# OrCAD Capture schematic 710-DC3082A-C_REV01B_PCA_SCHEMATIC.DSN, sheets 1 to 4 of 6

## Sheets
1 PAGE6: size A
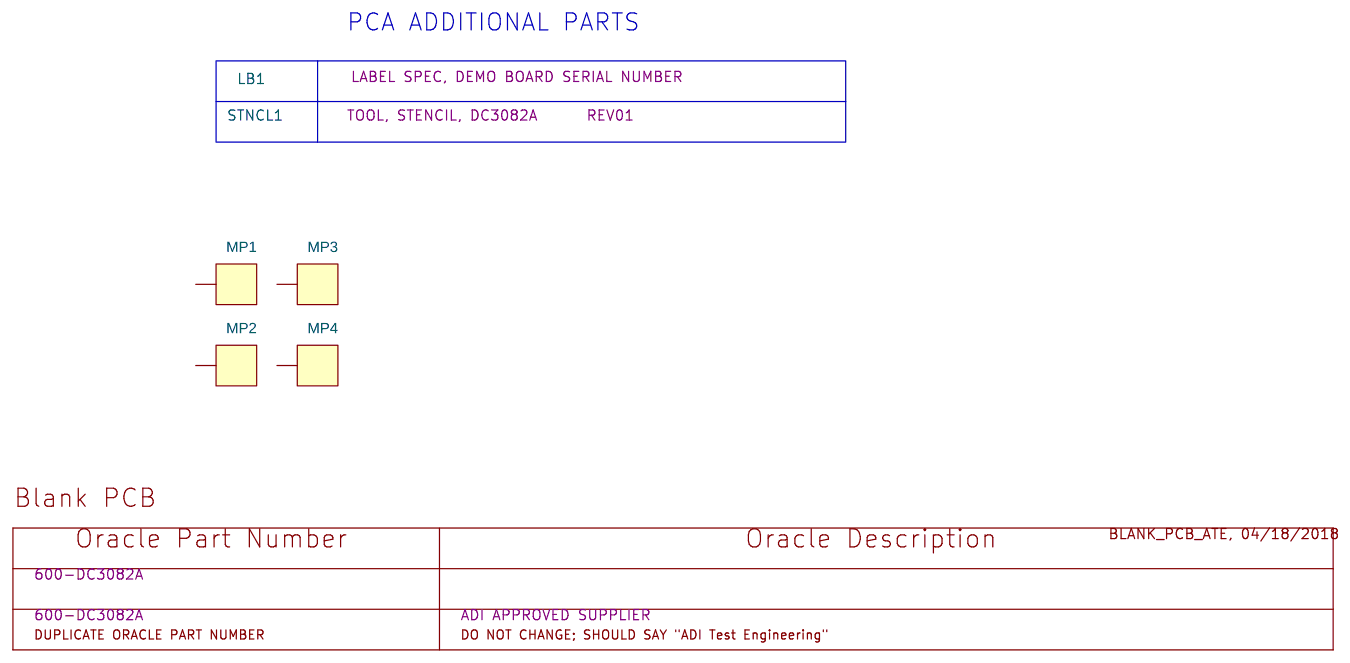
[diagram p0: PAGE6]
2 PAGE5: size Custom; rev: V1.0; company: WITH DIGITAL POWER MANAGEMENT; note: POLYPHASE SINGLE OUTPUT DC/DC PSM
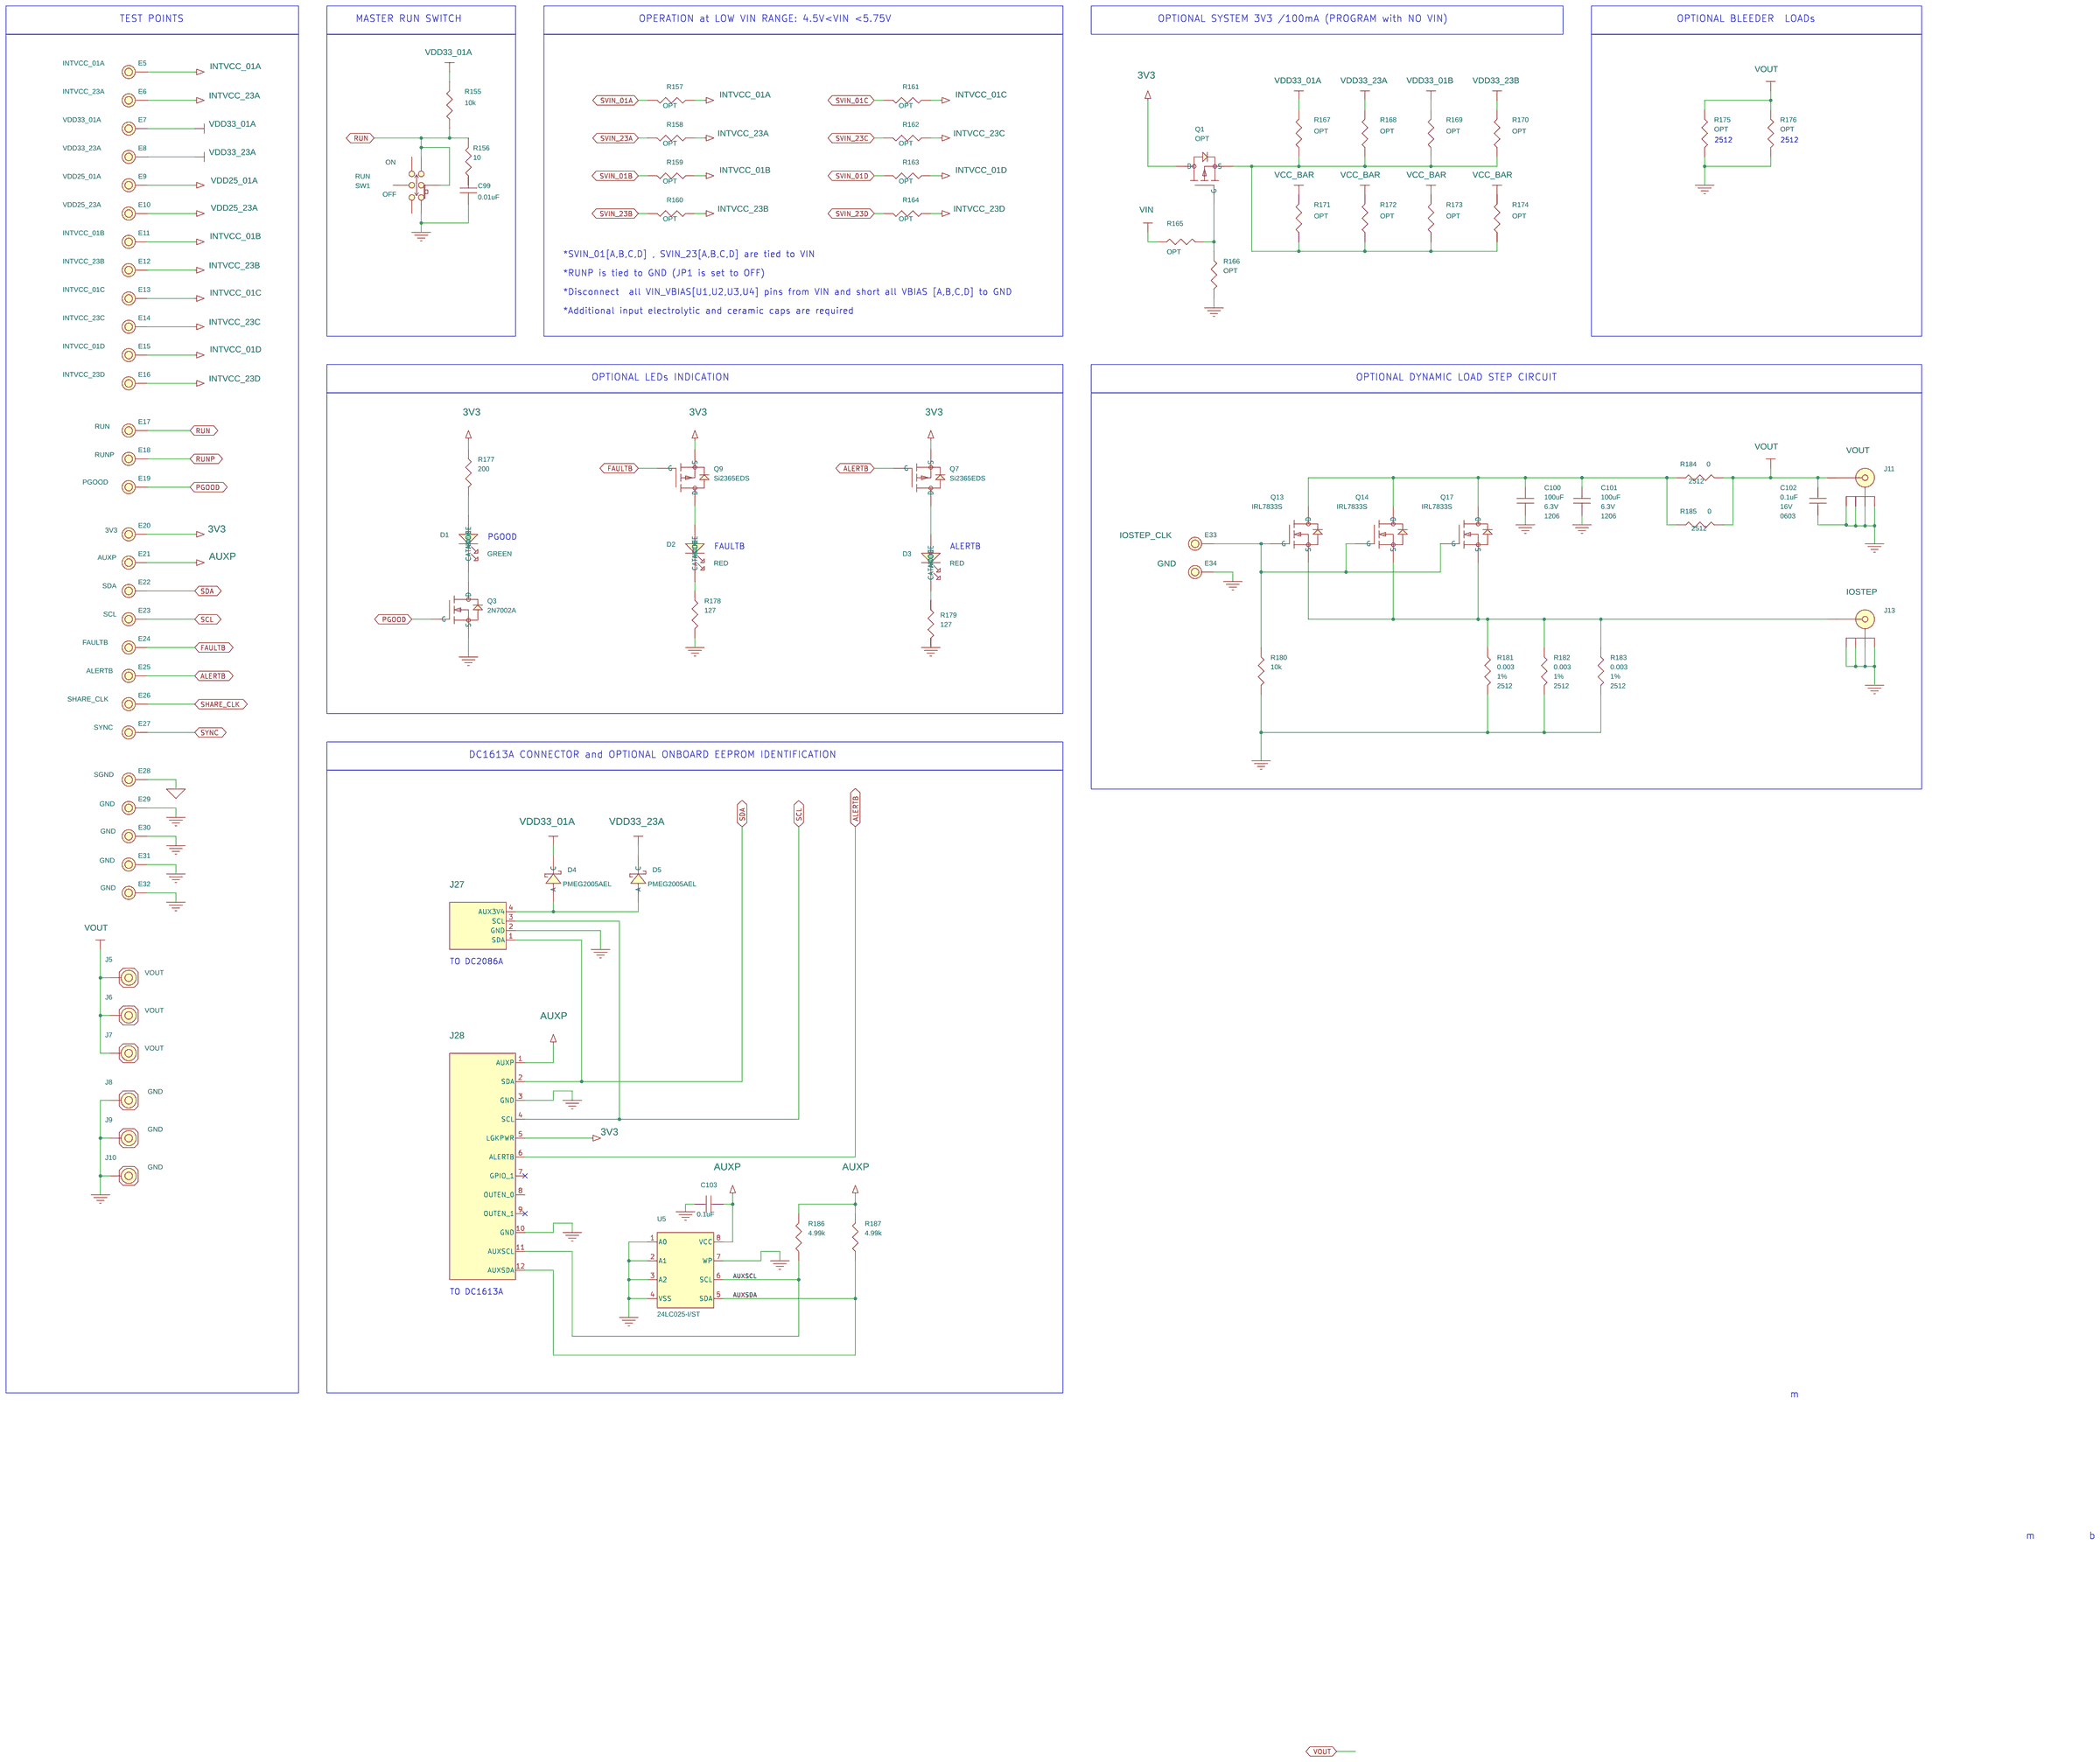
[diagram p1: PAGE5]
3 PAGE4: size Custom; rev: V1.0; company: WITH DIGITAL POWER MANAGEMENT; note: POLYPHASE SINGLE OUTPUT DC/DC PSM
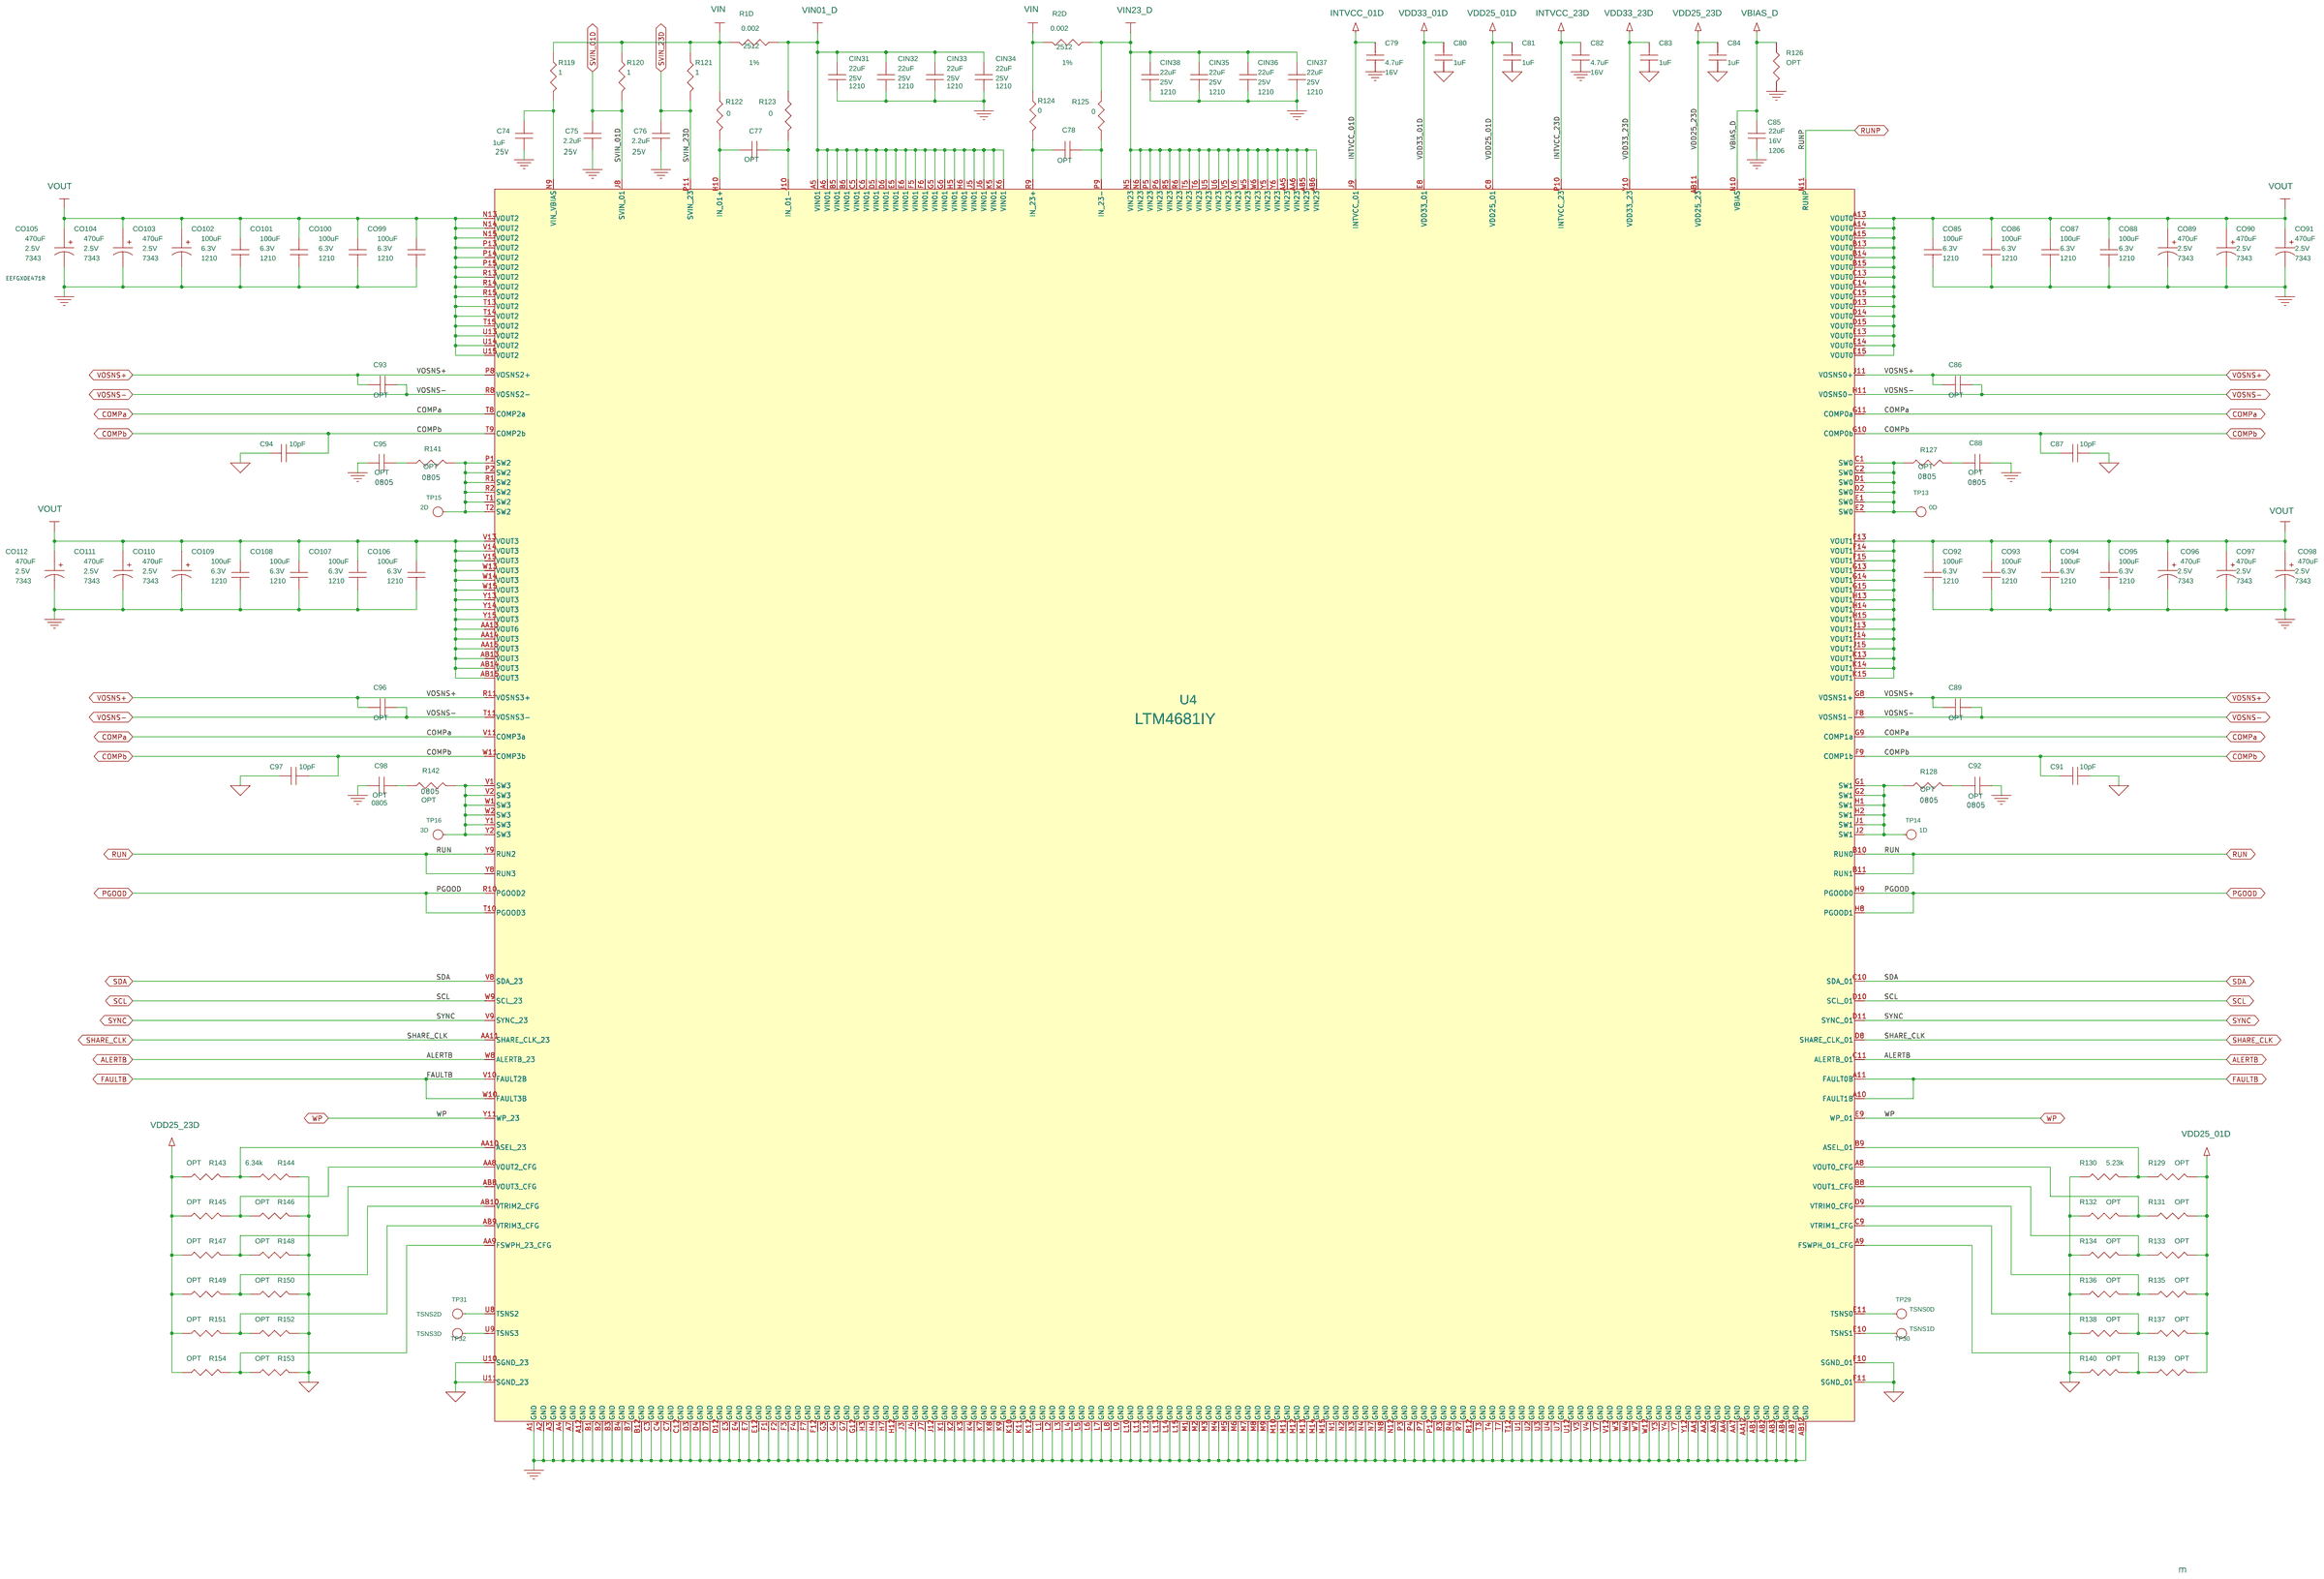
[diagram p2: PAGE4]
4 PAGE3: size Custom; rev: V1.0; company: WITH DIGITAL POWER MANAGEMENT; note: POLYPHASE SINGLE OUTPUT DC/DC PSM
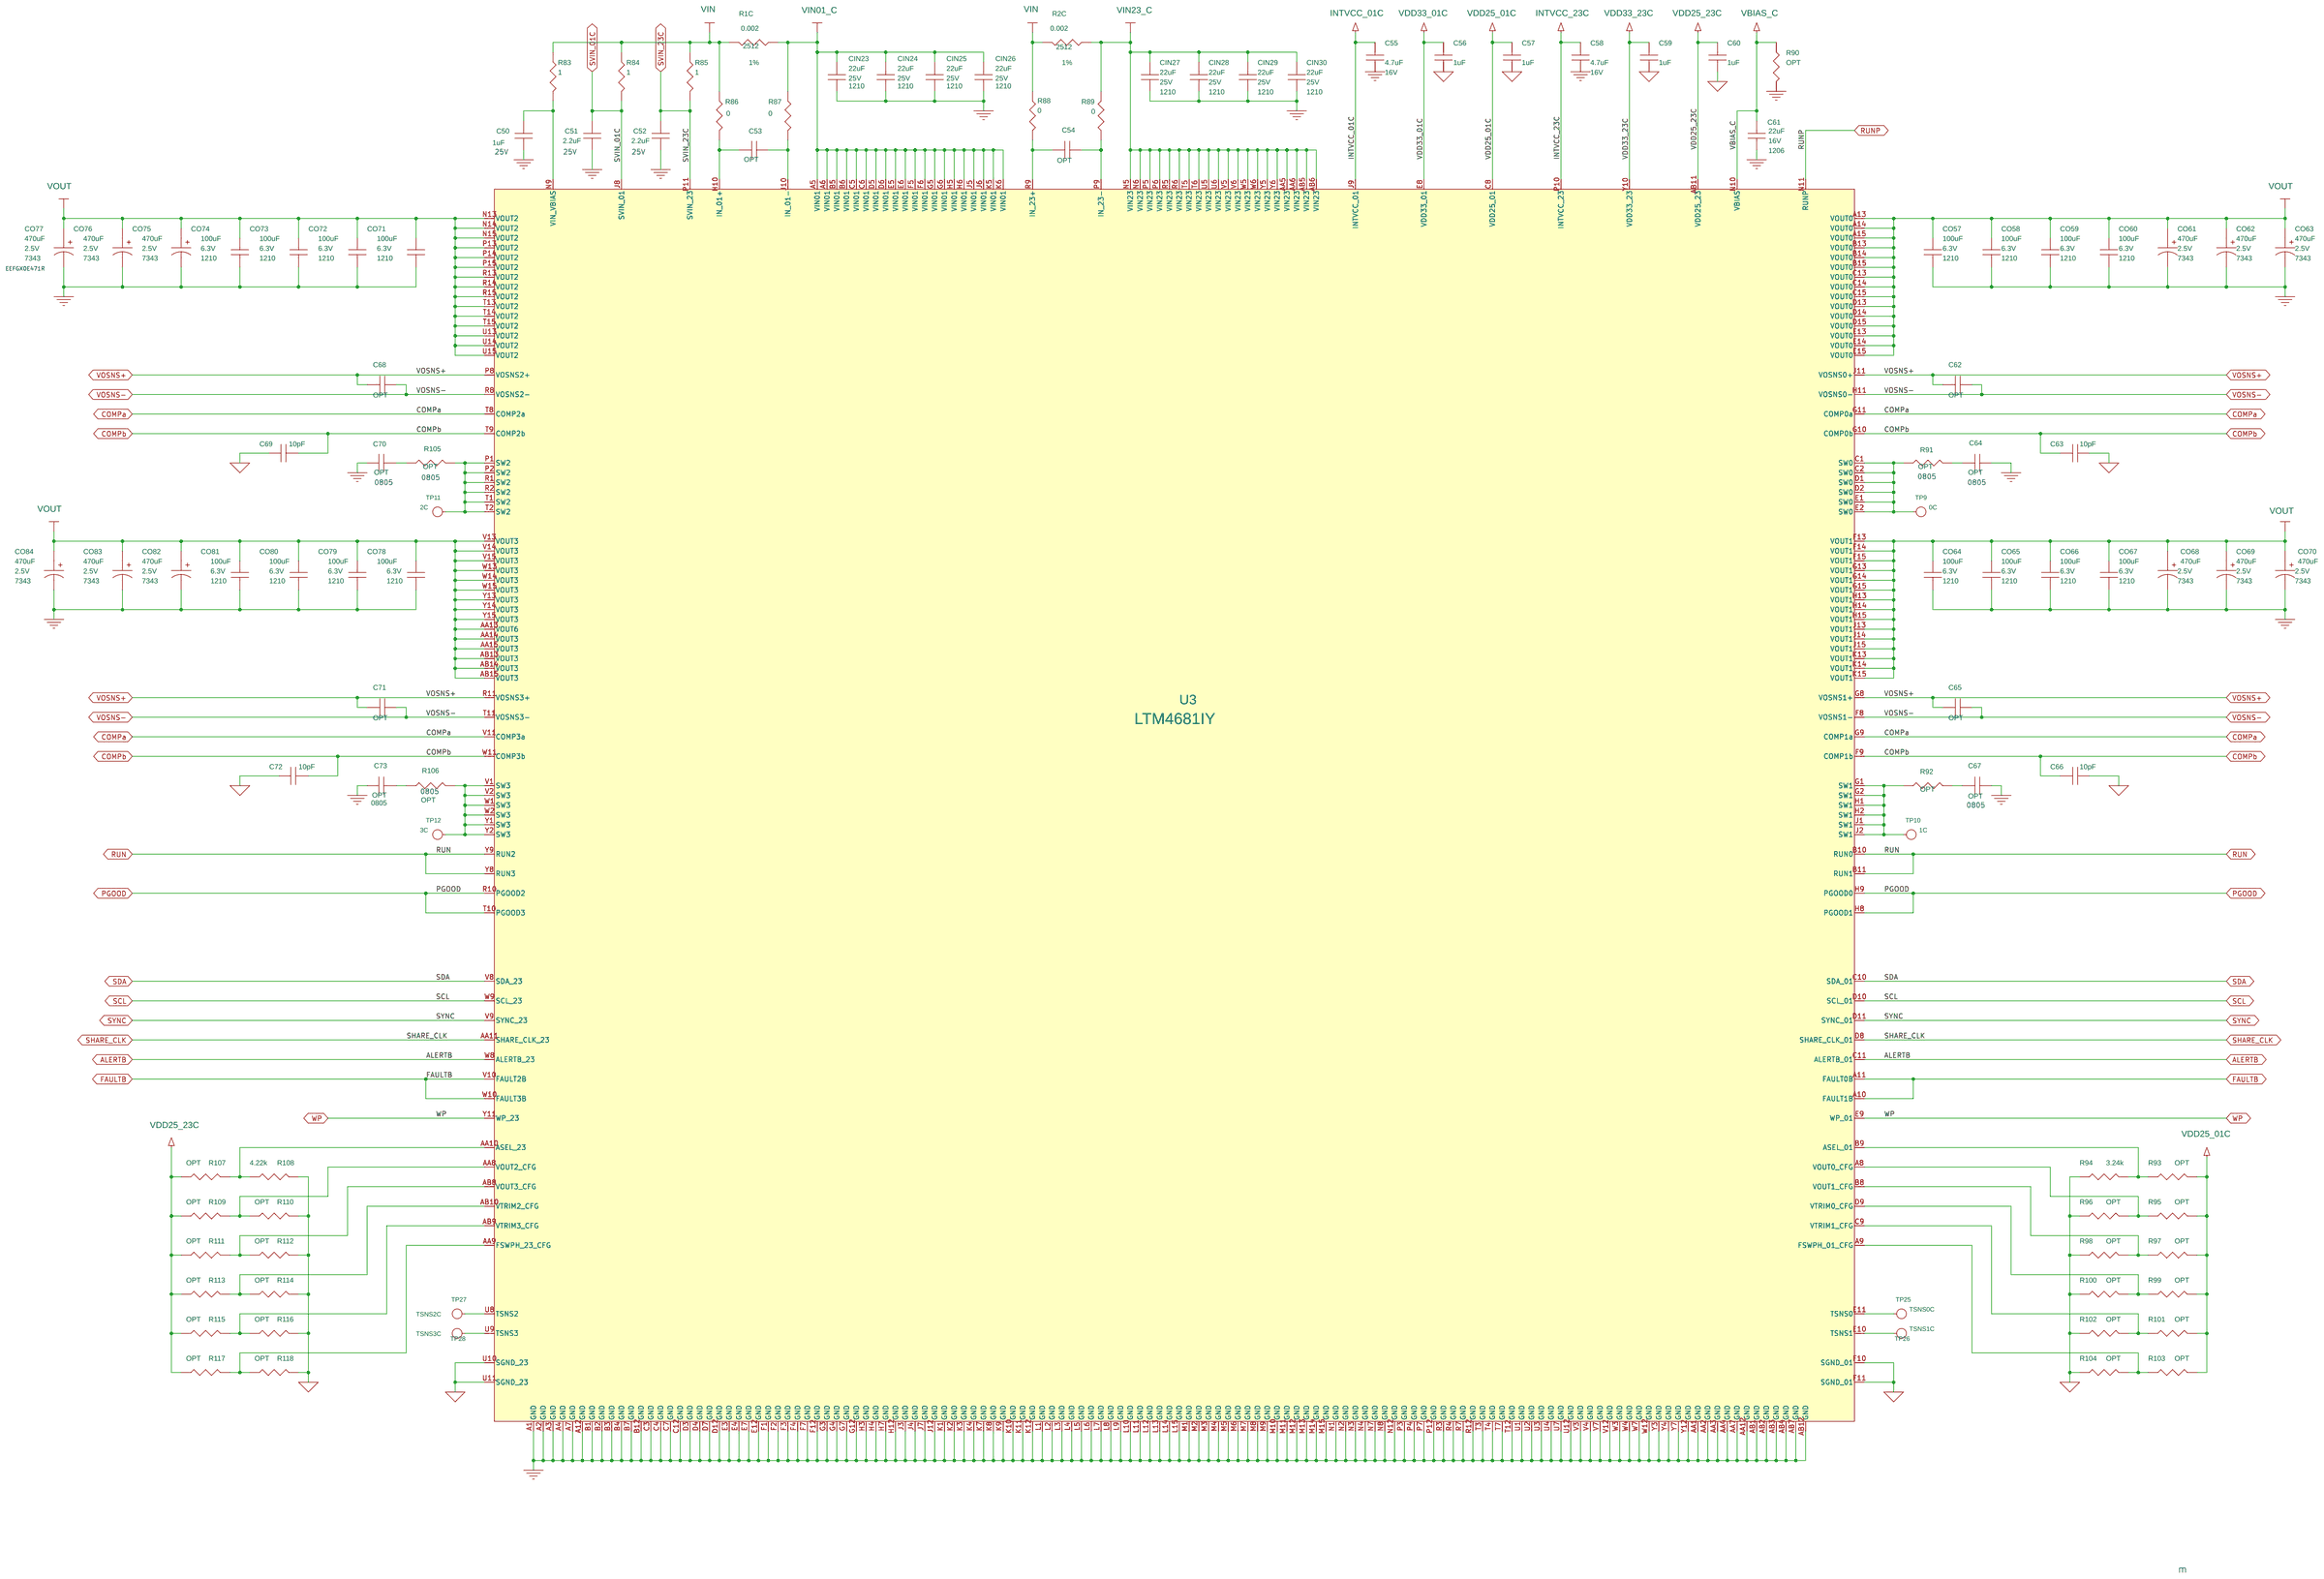
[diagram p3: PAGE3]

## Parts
sheet PAGE3
C50  1uF  [CC0603N]
C51  2.2uF  [CC0603N]
C52  2.2uF  [CC0603N]
C53  OPT  [CC0603N]
C54  OPT  [CC0603N]
C55  4.7uF  [CC0603N]
C56  1uF  [CC0603N]
C57  1uF  [CC0603N]
C58  4.7uF  [CC0603N]
C59  1uF  [CC0603N]
C60  1uF  [CC0603N]
C61  22uF  [CC1206N]
C62  OPT  [CC0603N]
C63  10pF  [CC0603N]
C64  OPT  [CC0805N]
C65  OPT  [CC0603N]
C66  10pF  [CC0603N]
C67  OPT  [CC0805N]
C68  OPT  [CC0603N]
C69  10pF  [CC0603N]
C70  OPT  [CC0805N]
C71  OPT  [CC0603N]
C72  10pF  [CC0603N]
C73  OPT  [CC0805N]
CIN23  22uF  [CC1210N]
CIN24  22uF  [CC1210N]
CIN25  22uF  [CC1210N]
CIN26  22uF  [CC1210N]
CIN27  22uF  [CC1210N]
CIN28  22uF  [CC1210N]
CIN29  22uF  [CC1210N]
CIN30  22uF  [CC1210N]
CO57  100uF  [CC1210N]
CO58  100uF  [CC1210N]
CO59  100uF  [CC1210N]
CO60  100uF  [CC1210N]
CO61  470uF  [CAPMP7343N]
CO62  470uF  [CAPMP7343N]
CO63  470uF  [CAPMP7343N]
CO64  100uF  [CC1210N]
CO65  100uF  [CC1210N]
CO66  100uF  [CC1210N]
CO67  100uF  [CC1210N]
CO68  470uF  [CAPMP7343N]
CO69  470uF  [CAPMP7343N]
CO70  470uF  [CAPMP7343N]
CO71  100uF  [CC1210N]
CO72  100uF  [CC1210N]
CO73  100uF  [CC1210N]
CO74  100uF  [CC1210N]
CO75  470uF  [CAPMP7343N]
CO76  470uF  [CAPMP7343N]
CO77  470uF  [CAPMP7343N]
CO78  100uF  [CC1210N]
CO79  100uF  [CC1210N]
CO80  100uF  [CC1210N]
CO81  100uF  [CC1210N]
CO82  470uF  [CAPMP7343N]
CO83  470uF  [CAPMP7343N]
CO84  470uF  [CAPMP7343N]
R1C  0.002  [CR2512N]
R2C  0.002  [CR2512N]
R83  1  [CR0603N]
R84  1  [CR0603N]
R85  1  [CR0603N]
R86  0  [CR0603N]
R87  0  [CR0603N]
R88  0  [CR0603N]
R89  0  [CR0603N]
R90  OPT  [CR0603N]
R91  OPT  [CR0805N]
R92  OPT  [CR0805N]
R93  OPT  [CR0603N]
R94  3.24k  [CR0603N]
R95  OPT  [CR0603N]
R96  OPT  [CR0603N]
R97  OPT  [CR0603N]
R98  OPT  [CR0603N]
R99  OPT  [CR0603N]
R100  OPT  [CR0603N]
R101  OPT  [CR0603N]
R102  OPT  [CR0603N]
R103  OPT  [CR0603N]
R104  OPT  [CR0603N]
R105  OPT  [CR0805N]
R106  OPT  [CR0805N]
R107  OPT  [CR0603N]
R108  4.22k  [CR0603N]
R109  OPT  [CR0603N]
R110  OPT  [CR0603N]
R111  OPT  [CR0603N]
R112  OPT  [CR0603N]
R113  OPT  [CR0603N]
R114  OPT  [CR0603N]
R115  OPT  [CR0603N]
R116  OPT  [CR0603N]
R117  OPT  [CR0603N]
R118  OPT  [CR0603N]
TP9  0C  [TP-.762MM]
TP10  1C  [TP-.762MM]
TP11  2C  [TP-.762MM]
TP12  3C  [TP-.762MM]
TP25  TSNS0C  [TP-.762MM]
TP26  TSNS1C  [TP-.762MM]
TP27  TSNS2C  [TP-.762MM]
TP28  TSNS3C  [TP-.762MM]
U3  LTM4681IY  [LTC-BGA-330-4681Y]
sheet PAGE4
C74  1uF  [CC0603N]
C75  2.2uF  [CC0603N]
C76  2.2uF  [CC0603N]
C77  OPT  [CC0603N]
C78  OPT  [CC0603N]
C79  4.7uF  [CC0603N]
C80  1uF  [CC0603N]
C81  1uF  [CC0603N]
C82  4.7uF  [CC0603N]
C83  1uF  [CC0603N]
C84  1uF  [CC0603N]
C85  22uF  [CC1206N]
C86  OPT  [CC0603N]
C87  10pF  [CC0603N]
C88  OPT  [CC0805N]
C89  OPT  [CC0603N]
C91  10pF  [CC0603N]
C92  OPT  [CC0805N]
C93  OPT  [CC0603N]
C94  10pF  [CC0603N]
C95  OPT  [CC0805N]
C96  OPT  [CC0603N]
C97  10pF  [CC0603N]
C98  OPT  [CC0805N]
CIN31  22uF  [CC1210N]
CIN32  22uF  [CC1210N]
CIN33  22uF  [CC1210N]
CIN34  22uF  [CC1210N]
CIN35  22uF  [CC1210N]
CIN36  22uF  [CC1210N]
CIN37  22uF  [CC1210N]
CIN38  22uF  [CC1210N]
CO85  100uF  [CC1210N]
CO86  100uF  [CC1210N]
CO87  100uF  [CC1210N]
CO88  100uF  [CC1210N]
CO89  470uF  [CAPMP7343N]
CO90  470uF  [CAPMP7343N]
CO91  470uF  [CAPMP7343N]
CO92  100uF  [CC1210N]
CO93  100uF  [CC1210N]
CO94  100uF  [CC1210N]
CO95  100uF  [CC1210N]
CO96  470uF  [CAPMP7343N]
CO97  470uF  [CAPMP7343N]
CO98  470uF  [CAPMP7343N]
CO99  100uF  [CC1210N]
CO100  100uF  [CC1210N]
CO101  100uF  [CC1210N]
CO102  100uF  [CC1210N]
CO103  470uF  [CAPMP7343N]
CO104  470uF  [CAPMP7343N]
CO105  470uF  [CAPMP7343N]
CO106  100uF  [CC1210N]
CO107  100uF  [CC1210N]
CO108  100uF  [CC1210N]
CO109  100uF  [CC1210N]
CO110  470uF  [CAPMP7343N]
CO111  470uF  [CAPMP7343N]
CO112  470uF  [CAPMP7343N]
R1D  0.002  [CR2512N]
R2D  0.002  [CR2512N]
R119  1  [CR0603N]
R120  1  [CR0603N]
R121  1  [CR0603N]
R122  0  [CR0603N]
R123  0  [CR0603N]
R124  0  [CR0603N]
R125  0  [CR0603N]
R126  OPT  [CR0603N]
R127  OPT  [CR0805N]
R128  OPT  [CR0805N]
R129  OPT  [CR0603N]
R130  5.23k  [CR0603N]
R131  OPT  [CR0603N]
R132  OPT  [CR0603N]
R133  OPT  [CR0603N]
R134  OPT  [CR0603N]
R135  OPT  [CR0603N]
R136  OPT  [CR0603N]
R137  OPT  [CR0603N]
R138  OPT  [CR0603N]
R139  OPT  [CR0603N]
R140  OPT  [CR0603N]
R141  OPT  [CR0805N]
R142  OPT  [CR0805N]
R143  OPT  [CR0603N]
R144  6.34k  [CR0603N]
R145  OPT  [CR0603N]
R146  OPT  [CR0603N]
R147  OPT  [CR0603N]
R148  OPT  [CR0603N]
R149  OPT  [CR0603N]
R150  OPT  [CR0603N]
R151  OPT  [CR0603N]
R152  OPT  [CR0603N]
R153  OPT  [CR0603N]
R154  OPT  [CR0603N]
TP13  0D  [TP-.762MM]
TP14  1D  [TP-.762MM]
TP15  2D  [TP-.762MM]
TP16  3D  [TP-.762MM]
TP29  TSNS0D  [TP-.762MM]
TP30  TSNS1D  [TP-.762MM]
TP31  TSNS2D  [TP-.762MM]
TP32  TSNS3D  [TP-.762MM]
U4  LTM4681IY  [LTC-BGA-330-4681Y]
sheet PAGE5
C99  0.01uF  [CC0603N]
C100  100uF  [CC1206N]
C101  100uF  [CC1206N]
C102  0.1uF  [CC0603N]
C103  0.1uF  [CC0603N]
D1  GREEN  [LED_0603]
D2  RED  [LED_0603]
D3  RED  [LED_0603]
D4  PMEG2005AEL  [SOD-882N]
D5  PMEG2005AEL  [SOD-882N]
E5  TEST POINT  [MILLMAX2501]
E6  TEST POINT  [MILLMAX2501]
E7  TEST POINT  [MILLMAX2501]
E8  TEST POINT  [MILLMAX2501]
E9  TEST POINT  [MILLMAX2501]
E10  TEST POINT  [MILLMAX2501]
E11  TEST POINT  [MILLMAX2501]
E12  TEST POINT  [MILLMAX2501]
E13  TEST POINT  [MILLMAX2501]
E14  TEST POINT  [MILLMAX2501]
E15  TEST POINT  [MILLMAX2501]
E16  TEST POINT  [MILLMAX2501]
E17  TEST POINT  [MILLMAX2501]
E18  TEST POINT  [MILLMAX2501]
E19  TEST POINT  [MILLMAX2501]
E20  TEST POINT  [MILLMAX2501]
E21  TEST POINT  [MILLMAX2501]
E22  TEST POINT  [MILLMAX2501]
E23  TEST POINT  [MILLMAX2501]
E24  TEST POINT  [MILLMAX2501]
E25  TEST POINT  [MILLMAX2501]
E26  TEST POINT  [MILLMAX2501]
E27  TEST POINT  [MILLMAX2501]
E28  TEST POINT  [MILLMAX2501]
E29  TEST POINT  [MILLMAX2501]
E30  TEST POINT  [MILLMAX2501]
E31  TEST POINT  [MILLMAX2501]
E32  TEST POINT  [MILLMAX2501]
E33  TEST POINT  [MILLMAX2501]
E34  TEST POINT  [MILLMAX2501]
J5  STUD,#10-32  [PENN-KFH-032]
J6  STUD,#10-32  [PENN-KFH-032]
J7  STUD,#10-32  [PENN-KFH-032]
J8  STUD,#10-32  [PENN-KFH-032]
J9  STUD,#10-32  [PENN-KFH-032]
J10  STUD,#10-32  [PENN-KFH-032]
J11  RF,BNC  [CONNEX-112404]
J13  RF,BNC  [CONNEX-112404]
J27  HDR,SHROUDED  [HIROSE-DF3A-4P-2DSA]
J28  HDR,SHROUDED  [HD2X6-079-MOLEX]
Q1  OPT  [SOT23-3N]
Q3  2N7002A  [SOT23-3N]
Q7  Si2365EDS  [SOT23-3N]
Q9  Si2365EDS  [SOT23-3N]
Q13  IRL7833S  [IRF-D2PAK]
Q14  IRL7833S  [IRF-D2PAK]
Q17  IRL7833S  [IRF-D2PAK]
R155  10k  [CR0603N]
R156  10  [CR0603N]
R157  OPT  [CR0603N]
R158  OPT  [CR0603N]
R159  OPT  [CR0603N]
R160  OPT  [CR0603N]
R161  OPT  [CR0603N]
R162  OPT  [CR0603N]
R163  OPT  [CR0603N]
R164  OPT  [CR0603N]
R165  OPT  [CR0603N]
R166  OPT  [CR0603N]
R167  OPT  [CR0603N]
R168  OPT  [CR0603N]
R169  OPT  [CR0603N]
R170  OPT  [CR0603N]
R171  OPT  [CR0603N]
R172  OPT  [CR0603N]
R173  OPT  [CR0603N]
R174  OPT  [CR0603N]
R175  OPT  [CR2512N]
R176  OPT  [CR2512N]
R177  200  [CR0603N]
R178  127  [CR0603N]
R179  127  [CR0603N]
R180  10k  [CR0603N]
R181  0.003  [PANASONIC-ERJM1WS]
R182  0.003  [PANASONIC-ERJM1WS]
R183  0.003  [PANASONIC-ERJM1WS]
R184  0  [VISHAY-WSL_9-2512]
R185  0  [VISHAY-WSL_9-2512]
R186  4.99k  [CR0603N]
R187  4.99k  [CR0603N]
SW1  DPDT  [CK-JS202011CQN]
U5  24LC025-I/ST  [MO-153AA_N]
sheet PAGE6
LB1  LABEL  [895-0154_REV01]
MP1  STANDOFF  [KEYSTONE_8829-8834]
MP2  STANDOFF  [KEYSTONE_8829-8834]
MP3  STANDOFF  [KEYSTONE_8829-8834]
MP4  STANDOFF  [KEYSTONE_8829-8834]
PCB1  PCB, DC3082A
STNCL1  TOOL, STENCIL, DC3082A

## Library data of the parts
C50 C56 C57 C59 C60 C74 C80 C81 C83 C84 = CAP: CAP.,1uF,X7R,25V,10%,0603,AEC-Q200; CLASS: DISCRETE; Dielectric Type: X7R; FPLIST: CC0603N,CC0603L,CC0603M; Inventory Qty: 53700; Manufacturer: MURATA; Manufacturer PN: GCM188R71E105KA64D; PART_NUMBER: 150-0291; Package Size: 0603; Rated Voltage: 25V; Tolerance: 10%
C51 C52 C75 C76 = CAP: CAP.,2.2uF,X5R,25V,10%,0603; CLASS: DISCRETE; Dielectric Type: X5R; FPLIST: CC0603N,CC0603L,CC0603M; Inventory Qty: 35022; Manufacturer: MURATA; Manufacturer PN: GRM188R61E225KA12D; PART_NUMBER: 150-3289; Package Size: 0603; Rated Voltage: 25V; Tolerance: 10%
C53 C54 C62 C65 C68 C71 C77 C78 C86 C89 C93 C96 = CAP: CAP., OPTION, 0603; CLASS: DISCRETE; FPLIST: CC0603N,CC0603L,CC0603M; PART_NUMBER: 150-3038; Package Size: 0603; Package Type: SMD
C55 C58 C79 C82 = CAP: CAP.,4.7uF,X5R,16V,10%,0603; CLASS: DISCRETE; Dielectric Type: X5R; FPLIST: CC0603N,CC0603L,CC0603M; Inventory Qty: 44050; Manufacturer: MURATA; Manufacturer PN: GRM188R61C475KAAJD; PART_NUMBER: 150-3182; Package Size: 0603; Rated Voltage: 16V; Tolerance: 10%
C61 C85 = CAP: CAP.,22uF,X5R,16V,10%,1206; CLASS: DISCRETE; Dielectric Type: X5R; FPLIST: CC1206N,CC1206L,CC1206M; Inventory Qty: 6429; Manufacturer: AVX; Manufacturer PN: 1206YD226KAT2A; PART_NUMBER: 150-3044; Package Size: 1206; Rated Voltage: 16V; Tolerance: 10%
C63 C66 C69 C72 C87 C91 C94 C97 = CAP: CAP.,10pF,C0G,50V,5%,0603; CLASS: DISCRETE; Dielectric Type: C0G; FPLIST: CC0603N,CC0603L,CC0603M; Inventory Qty: 17004; Manufacturer: AVX; Manufacturer PN: 06035A100JAT2A; PART_NUMBER: 150-0280; Package Size: 0603; Rated Voltage: 50V; Tolerance: 5%
C64 C67 C70 C73 C88 C92 C95 C98 = CAP: CAP., OPTION, 0805; CLASS: DISCRETE; FPLIST: CC0805N,CC0805L,CC0805M; PART_NUMBER: 150-3036; Package Size: 0805; Package Type: SMD
CIN23-CIN38 = CAP: CAP.,22uF,X5R,25V,10%,1210; CLASS: DISCRETE; Dielectric Type: X5R; FPLIST: CC1210N,CC1210L,CC1210M; Inventory Qty: 26336; Manufacturer: KEMET; Manufacturer PN: C1210C226K3PACTU; PART_NUMBER: 150-3033; Package Size: 1210; Package Type: SMD; Rated Voltage: 25V; Tolerance: 10%
CO57-CO60 CO64-CO67 CO71-CO74 CO78-CO81 CO85-CO88 CO92-CO95 CO99-CO102 CO106-CO109 = CAP: CAP.,100uF,X5R,6.3V,20%,1210; CLASS: DISCRETE; Dielectric Type: X5R; FPLIST: CC1210N,CC1210L,CC1210M; Inventory Qty: 50440; Manufacturer: AVX; Manufacturer PN: 12106D107MAT2A; PART_NUMBER: 150-3008; Package Size: 1210; Rated Voltage: 6.3V; Tolerance: 20%
CO61-CO63 CO68-CO70 CO75 CO76 CO82 CO83 CO89-CO91 CO96-CO98 CO103 CO104 CO110 CO111 = CAP_P_ALT: CAP.,470uF,TANT,POSCAP,2.5V,20%,7343,TPF Series; CLASS: DISCRETE; Dielectric Type: TANT,POSCAP; FPLIST: CAPMP7343N,CAPMP7343L,CAPMP7343M; Inventory Qty: 26416; Manufacturer: PANASONIC; Manufacturer PN: ETPF470M5H; PART_NUMBER: 150-2629; Package Size: 7343; Rated Voltage: 2.5V; Tolerance: 20%
CO77 CO105 = CAP_P_ALT: CAP.,470uF,TANT,POSCAP,2.5V,20%,7343,TPF Series; CLASS: DISCRETE; Dielectric Type: TANT,POSCAP; FPLIST: CAPMP7343N,CAPMP7343L,CAPMP7343M; Inventory Qty: 26416; Manufacturer: PANASONIC; Manufacturer PN: ETPF470M5H; PART_FIELD_01: 2.5V; PART_NUMBER: 150-2629; Package Size: 7343; Rated Voltage: 2.5V; Tolerance: 20%
CO84 CO112 = CAP_P_ALT: CAP.,470uF,TANT,POSCAP,2.5V,20%,7343,TPF Series; BOM Notes: COUT1,COUT6=6.3V; CLASS: DISCRETE; Dielectric Type: TANT,POSCAP; FPLIST: CAPMP7343N,CAPMP7343L,CAPMP7343M; Inventory Qty: 26416; Manufacturer: PANASONIC; Manufacturer PN: ETPF470M5H; PART_FIELD_01: 2.5V; PART_NUMBER: 150-2629; Package Size: 7343; Rated Voltage: 2.5V; Tolerance: 20%
R1C R1D R2C R2D = RES: RES.,0.002 OHM,1%,1W,2512,SENSE; CLASS: DISCRETE; FPLIST: CR2512N,CR2512L,CR2512M; Inventory Qty: 4998; Manufacturer: VISHAY; Manufacturer PN: WSL25122L000FEA; PART_NUMBER: 100-0062; Package Size: 2512; Rated Power: 1W; Temperature Coefficient: 275ppm/C; Tolerance: 1%
R83-R85 R119-R121 = RES: RES.,1 OHM,1%,1/10W,0603,AEC-Q200; CLASS: DISCRETE; FPLIST: CR0603N,CR0603L,CR0603M; Inventory Qty: 53360; Manufacturer: NIC; Manufacturer PN: NRC06F1R00TRF; PART_NUMBER: 100-0238; Package Size: 0603; Rated Power: 1/10W; Temperature Coefficient: 100ppm/C; Tolerance: 1%
R86-R89 R122-R125 = RES: RES.,0 OHM,1/10W,0603,AEC-Q200; CLASS: DISCRETE; FPLIST: CR0603N,CR0603L,CR0603M; Inventory Qty: 700742; Manufacturer: VISHAY; Manufacturer PN: CRCW06030000Z0EA; PART_NUMBER: 100-0009; Package Size: 0603; Rated Power: 1/10W
R90 R93 R95-R104 R107 R109-R118 R126 R129 R131-R140 R143 R145-R154 R157-R174 = RES: RES., OPTION, 0603; CLASS: DISCRETE; FPLIST: CR0603N,CR0603L,CR0603M; PART_NUMBER: 100-2374; Package Size: 0603
R91 R92 R105 R106 R127 R128 R141 R142 = RES: RES., OPTION, 0805; CLASS: DISCRETE; FPLIST: CR0805N,CR0805L,CR0805M; PART_NUMBER: 100-2558; Package Size: 0805
R94 = RES: RES.,3.24k OHMS,1%,1/10W,0603; CLASS: DISCRETE; FPLIST: CR0603N,CR0603L,CR0603M; Inventory Qty: 14995; Manufacturer: YAGEO; Manufacturer PN: RC0603FR-073K24L; PART_NUMBER: 100-2722; Package Size: 0603; Rated Power: 1/10W; Temperature Coefficient: 100ppm/C; Tolerance: 1%
R108 = RES: RES.,4.22k OHMS,1%,1/10W,0603; CLASS: DISCRETE; FPLIST: CR0603N,CR0603L,CR0603M; Inventory Qty: 19940; Manufacturer: NIC; Manufacturer PN: NRC06F4221TRF; PART_NUMBER: 100-2720; Package Size: 0603; Rated Power: 1/10W; Temperature Coefficient: 100ppm/C; Tolerance: 1%
TP9-TP16 TP25-TP32 = E-100SMT
U3 U4 = LTM4681-BGA_1: IC,QUAD OUTPUT uMODULE REG.,BGA; CLASS: IC; Inventory Qty: 0; Manufacturer: ANALOG DEVICES; Manufacturer PN: LTM4681EY#PBF; PART_NUMBER: LTM4681EY#PBF; Package Type: BGA
R130 = RES: RES.,5.23k OHMS,1%,1/10W,0603,AEC-Q200; CLASS: DISCRETE; FPLIST: CR0603N,CR0603L,CR0603M; Inventory Qty: 28495; Manufacturer: PANASONIC; Manufacturer PN: ERJ3EKF5231V; PART_NUMBER: 100-0891; Package Size: 0603; Rated Power: 1/10W; Temperature Coefficient: +/-100PPM; Tolerance: 1%
R144 = RES: RES.,6.34k OHMS,1%,1/10W,0603,AEC-Q200; CLASS: DISCRETE; FPLIST: CR0603N,CR0603L,CR0603M; Inventory Qty: 54970; Manufacturer: KOA SPEER; Manufacturer PN: RK73H1JTTD6341F; PART_NUMBER: 100-0997; Package Size: 0603; Rated Power: 1/10W; Temperature Coefficient: 100ppm; Tolerance: 1%
C99 = CAP: CAP.,0.01uF,X7R,50V,10%,0603; CLASS: DISCRETE; Dielectric Type: X7R; FPLIST: CC0603N,CC0603L,CC0603M; Inventory Qty: 28483; Manufacturer: AVX; Manufacturer PN: 06035C103KAT2A; PART_NUMBER: 150-0002; Package Size: 0603; Rated Voltage: 50V; Tolerance: 10%
C100 C101 = CAP: CAP.,100uF,X5R,6.3V,10%,1206; CLASS: DISCRETE; Dielectric Type: X5R; FPLIST: CC1206N,CC1206L,CC1206M; Inventory Qty: 5866; Manufacturer: MURATA; Manufacturer PN: GRM31CR60J107KE39L; PART_NUMBER: 150-2327; Package Size: 1206; Rated Voltage: 6.3V; Tolerance: 10%
C102 C103 = CAP: CAP.,0.1uF,X7R,16V,10%,0603,FLEXITERM; CLASS: DISCRETE; Dielectric Type: X7R; FPLIST: CC0603N,CC0603L,CC0603M; Inventory Qty: 23544; Manufacturer: AVX; Manufacturer PN: 0603YC104KAZ2A; PART_NUMBER: 150-0165; Package Size: 0603; Rated Voltage: 16V; Tolerance: 10%
D1 = LED: LED,GREEN,WATER CLEAR,0603; CLASS: DISCRETE; Inventory Qty: 10859; Manufacturer: WURTH ELEKTRONIK; Manufacturer PN: 150060GS75000; PART_NUMBER: 270-0057; Package Type: 0603
D2 D3 = LED: LED,RED,WATER CLEAR,0603; CLASS: DISCRETE; Inventory Qty: 17176; Label: GREEN; Manufacturer: WURTH ELEKTRONIK; Manufacturer PN: 150060RS75000; PART_NUMBER: 270-0071; Package Type: 0603
D4 D5 = DIODE_SCHOTTKY_A: DIODE,SCHOTTKY,20V,0.5A,SOD-882,LEADLESS; CLASS: DISCRETE; Inventory Qty: 13051; Manufacturer: NEXPERIA; Manufacturer PN: PMEG2005AEL,315; Max Forward Current or Rated Power: 0.5A; PART_NUMBER: 210-0105; Package Type: SOD-882; Rated Voltage: 20V; Rated Voltage or Zener Voltage: 20V
E5 = TESTPOINT_1.219_MILL-MAX_2501: TEST POINT,TURRET,0.094" MTG. HOLE,PCB 0.062" THK; 9th Part Field: INTVCC_01A; CLASS: IO; Inventory Qty: 823526; Manufacturer: MILL-MAX; Manufacturer PN: 2501-2-00-80-00-00-07-0; PART_NUMBER: 260-0003
E6 = TESTPOINT_1.219_MILL-MAX_2501: TEST POINT,TURRET,0.094" MTG. HOLE,PCB 0.062" THK; 9th Part Field: INTVCC_23A; CLASS: IO; Inventory Qty: 823526; Manufacturer: MILL-MAX; Manufacturer PN: 2501-2-00-80-00-00-07-0; PART_NUMBER: 260-0003
E7 = TESTPOINT_1.219_MILL-MAX_2501: TEST POINT,TURRET,0.094" MTG. HOLE,PCB 0.062" THK; 9th Part Field: VDD33_01A; CLASS: IO; Inventory Qty: 823526; Manufacturer: MILL-MAX; Manufacturer PN: 2501-2-00-80-00-00-07-0; PART_NUMBER: 260-0003
E8 = TESTPOINT_1.219_MILL-MAX_2501: TEST POINT,TURRET,0.094" MTG. HOLE,PCB 0.062" THK; 9th Part Field: VDD33_23A; CLASS: IO; Inventory Qty: 823526; Manufacturer: MILL-MAX; Manufacturer PN: 2501-2-00-80-00-00-07-0; PART_NUMBER: 260-0003
E9 = TESTPOINT_1.219_MILL-MAX_2501: TEST POINT,TURRET,0.094" MTG. HOLE,PCB 0.062" THK; 9th Part Field: VDD25_01A; CLASS: IO; Inventory Qty: 823526; Manufacturer: MILL-MAX; Manufacturer PN: 2501-2-00-80-00-00-07-0; PART_NUMBER: 260-0003
E10 = TESTPOINT_1.219_MILL-MAX_2501: TEST POINT,TURRET,0.094" MTG. HOLE,PCB 0.062" THK; 9th Part Field: VDD25_23A; CLASS: IO; Inventory Qty: 823526; Manufacturer: MILL-MAX; Manufacturer PN: 2501-2-00-80-00-00-07-0; PART_NUMBER: 260-0003
E11 = TESTPOINT_1.219_MILL-MAX_2501: TEST POINT,TURRET,0.094" MTG. HOLE,PCB 0.062" THK; 9th Part Field: INTVCC_01B; CLASS: IO; Inventory Qty: 823526; Manufacturer: MILL-MAX; Manufacturer PN: 2501-2-00-80-00-00-07-0; PART_NUMBER: 260-0003
E12 = TESTPOINT_1.219_MILL-MAX_2501: TEST POINT,TURRET,0.094" MTG. HOLE,PCB 0.062" THK; 9th Part Field: INTVCC_23B; CLASS: IO; Inventory Qty: 823526; Manufacturer: MILL-MAX; Manufacturer PN: 2501-2-00-80-00-00-07-0; PART_NUMBER: 260-0003
E13 = TESTPOINT_1.219_MILL-MAX_2501: TEST POINT,TURRET,0.094" MTG. HOLE,PCB 0.062" THK; 9th Part Field: INTVCC_01C; CLASS: IO; Inventory Qty: 823526; Manufacturer: MILL-MAX; Manufacturer PN: 2501-2-00-80-00-00-07-0; PART_NUMBER: 260-0003
E14 = TESTPOINT_1.219_MILL-MAX_2501: TEST POINT,TURRET,0.094" MTG. HOLE,PCB 0.062" THK; 9th Part Field: INTVCC_23C; CLASS: IO; Inventory Qty: 823526; Manufacturer: MILL-MAX; Manufacturer PN: 2501-2-00-80-00-00-07-0; PART_NUMBER: 260-0003
E15 = TESTPOINT_1.219_MILL-MAX_2501: TEST POINT,TURRET,0.094" MTG. HOLE,PCB 0.062" THK; 9th Part Field: INTVCC_01D; CLASS: IO; Inventory Qty: 823526; Manufacturer: MILL-MAX; Manufacturer PN: 2501-2-00-80-00-00-07-0; PART_NUMBER: 260-0003
E16 = TESTPOINT_1.219_MILL-MAX_2501: TEST POINT,TURRET,0.094" MTG. HOLE,PCB 0.062" THK; 9th Part Field: INTVCC_23D; CLASS: IO; Inventory Qty: 823526; Manufacturer: MILL-MAX; Manufacturer PN: 2501-2-00-80-00-00-07-0; PART_NUMBER: 260-0003
E17 = TESTPOINT_1.219_MILL-MAX_2501: TEST POINT,TURRET,0.094" MTG. HOLE,PCB 0.062" THK; 9th Part Field: RUN; CLASS: IO; Inventory Qty: 823526; Manufacturer: MILL-MAX; Manufacturer PN: 2501-2-00-80-00-00-07-0; PART_NUMBER: 260-0003
E18 = TESTPOINT_1.219_MILL-MAX_2501: TEST POINT,TURRET,0.094" MTG. HOLE,PCB 0.062" THK; 9th Part Field: RUNP; CLASS: IO; Inventory Qty: 823526; Manufacturer: MILL-MAX; Manufacturer PN: 2501-2-00-80-00-00-07-0; PART_NUMBER: 260-0003
E19 = TESTPOINT_1.219_MILL-MAX_2501: TEST POINT,TURRET,0.094" MTG. HOLE,PCB 0.062" THK; 9th Part Field: PGOOD; CLASS: IO; Inventory Qty: 823526; Manufacturer: MILL-MAX; Manufacturer PN: 2501-2-00-80-00-00-07-0; PART_NUMBER: 260-0003
E20 = TESTPOINT_1.219_MILL-MAX_2501: TEST POINT,TURRET,0.094" MTG. HOLE,PCB 0.062" THK; 9th Part Field: 3V3; CLASS: IO; Inventory Qty: 823526; Manufacturer: MILL-MAX; Manufacturer PN: 2501-2-00-80-00-00-07-0; PART_NUMBER: 260-0003
E21 = TESTPOINT_1.219_MILL-MAX_2501: TEST POINT,TURRET,0.094" MTG. HOLE,PCB 0.062" THK; 9th Part Field: AUXP; CLASS: IO; Inventory Qty: 823526; Manufacturer: MILL-MAX; Manufacturer PN: 2501-2-00-80-00-00-07-0; PART_NUMBER: 260-0003
E22 = TESTPOINT_1.219_MILL-MAX_2501: TEST POINT,TURRET,0.094" MTG. HOLE,PCB 0.062" THK; 9th Part Field: SDA; CLASS: IO; Inventory Qty: 823526; Manufacturer: MILL-MAX; Manufacturer PN: 2501-2-00-80-00-00-07-0; PART_NUMBER: 260-0003
E23 = TESTPOINT_1.219_MILL-MAX_2501: TEST POINT,TURRET,0.094" MTG. HOLE,PCB 0.062" THK; 9th Part Field: SCL; CLASS: IO; Inventory Qty: 823526; Manufacturer: MILL-MAX; Manufacturer PN: 2501-2-00-80-00-00-07-0; PART_NUMBER: 260-0003
E24 = TESTPOINT_1.219_MILL-MAX_2501: TEST POINT,TURRET,0.094" MTG. HOLE,PCB 0.062" THK; 9th Part Field: FAULTB; CLASS: IO; Inventory Qty: 823526; Manufacturer: MILL-MAX; Manufacturer PN: 2501-2-00-80-00-00-07-0; PART_NUMBER: 260-0003
E25 = TESTPOINT_1.219_MILL-MAX_2501: TEST POINT,TURRET,0.094" MTG. HOLE,PCB 0.062" THK; 9th Part Field: ALERTB; CLASS: IO; Inventory Qty: 823526; Manufacturer: MILL-MAX; Manufacturer PN: 2501-2-00-80-00-00-07-0; PART_NUMBER: 260-0003
E26 = TESTPOINT_1.219_MILL-MAX_2501: TEST POINT,TURRET,0.094" MTG. HOLE,PCB 0.062" THK; 9th Part Field: SHARE_CLK; CLASS: IO; Inventory Qty: 823526; Manufacturer: MILL-MAX; Manufacturer PN: 2501-2-00-80-00-00-07-0; PART_NUMBER: 260-0003
E27 = TESTPOINT_1.219_MILL-MAX_2501: TEST POINT,TURRET,0.094" MTG. HOLE,PCB 0.062" THK; 9th Part Field: SYNC; CLASS: IO; Inventory Qty: 823526; Manufacturer: MILL-MAX; Manufacturer PN: 2501-2-00-80-00-00-07-0; PART_NUMBER: 260-0003
E28 = TESTPOINT_1.219_MILL-MAX_2501: TEST POINT,TURRET,0.094" MTG. HOLE,PCB 0.062" THK; 9th Part Field: SGND; CLASS: IO; Inventory Qty: 823526; Manufacturer: MILL-MAX; Manufacturer PN: 2501-2-00-80-00-00-07-0; PART_NUMBER: 260-0003
E29-E32 E34 = TESTPOINT_1.219_MILL-MAX_2501: TEST POINT,TURRET,0.094" MTG. HOLE,PCB 0.062" THK; 9th Part Field: GND; CLASS: IO; Inventory Qty: 823526; Manufacturer: MILL-MAX; Manufacturer PN: 2501-2-00-80-00-00-07-0; PART_NUMBER: 260-0003
E33 = TESTPOINT_1.219_MILL-MAX_2501: TEST POINT,TURRET,0.094" MTG. HOLE,PCB 0.062" THK; 9th Part Field: IOSTEP_CLK; CLASS: IO; Inventory Qty: 823526; Manufacturer: MILL-MAX; Manufacturer PN: 2501-2-00-80-00-00-07-0; PART_NUMBER: 260-0003
J5-J7 = PEM-KFH: EVAL BOARD STUD HARDWARE SET, #10-32; 10th Part Field: 1V / ***A; 9th Part Field: VOUT; CLASS: DISCRETE; Comments: CONSISTS OF QTY(1) STUD, 769-0012; QTY(1) RING LUG, 769-0013;QTY(2) HEX NUT,BRASS,761-0013; QTY(1) WASHER,#10 LOCK, 762-0021; Manufacturer: ANALOG DEVICES; Manufacturer PN: 720-0010; PART_NUMBER: 720-0010
J8-J10 = PEM-KFH: EVAL BOARD STUD HARDWARE SET, #10-32; 9th Part Field: GND; CLASS: DISCRETE; Comments: CONSISTS OF QTY(1) STUD, 769-0012; QTY(1) RING LUG, 769-0013;QTY(2) HEX NUT,BRASS,761-0013; QTY(1) WASHER,#10 LOCK, 762-0021; Manufacturer: ANALOG DEVICES; Manufacturer PN: 720-0010; PART_NUMBER: 720-0010
J11 = BNC_50_OHM_112404_C: CONN.,RF,BNC,RCPT,JACK,5-PIN,ST,THT,50 OHMS; CLASS: IO; Inventory Qty: 80023; Manufacturer: AMPHENOL RF; Manufacturer PN: 112404; PART_FIELD_01: VOUT; PART_NUMBER: 250-0427
J13 = BNC_50_OHM_112404_C: CONN.,RF,BNC,RCPT,JACK,5-PIN,ST,THT,50 OHMS; CLASS: IO; Inventory Qty: 80023; Manufacturer: AMPHENOL RF; Manufacturer PN: 112404; PART_FIELD_01: IOSTEP; PART_NUMBER: 250-0427
J27 = CONN_DC2086: CONN.,HDR,SHROUDED,MALE,1x4,2mm,VERT,ST,THT; CLASS: IO; Inventory Qty: 5376; Manufacturer: HIROSE ELECTRIC; Manufacturer PN: DF3A-4P-2DSA; PART_NUMBER: 250-0491
J28 = CONN_7._FCI_12_POS_2MM: CONN.,HDR,SHROUDED,MALE,2x6,2mm,VERT,ST,THT; CLASS: IO; Inventory Qty: 12768; Manufacturer: AMPHENOL; Manufacturer PN: 98414-G06-12ULF; PART_NUMBER: 250-0433
Q1 = 3P_P-CH_TYPE1A: XSTR., OPTION, MOSFET, P-CH, SOT-23; CLASS: DISCRETE; FPLIST: SOT23-3N,SOT23-3L,SOT23-3M; PART_NUMBER: 240-0336; Package Type: SOT-23
Q3 = 3P_N-CH_TYPE1A: XSTR.,MOSFET,N-CH,60V,220mA,SOT23-3,AEC-Q101; CLASS: DISCRETE; FPLIST: SOT23-3N,SOT23-3L,SOT23-3M; Inventory Qty: 9660; Manufacturer: DIODES INC.; Manufacturer PN: 2N7002A-13; PART_NUMBER: 240-0059; Package Type: SOT23-3; Rated Voltage: 60V
Q7 Q9 = 3P_P-CH_TYPE1A: XSTR.,MOSFET,P-CH,20V,5.9A,SOT-23-3 (TO-236-3); CLASS: DISCRETE; FPLIST: SOT23-3N,SOT23-3L,SOT23-3M; Inventory Qty: 18908; Manufacturer: VISHAY; Manufacturer PN: Si2365EDS-T1-GE3; PART_NUMBER: 240-0119; Package Size: SOT-23; Package Type: SOT-23-3 (TO-236-3); Rated Voltage: 20V
Q13 Q14 Q17 = 3P_N-CH_TYPE2A: XSTR.,MOSFET,N-CH,30V,150A,D2PAK; CLASS: DISCRETE; Inventory Qty: 450; Manufacturer: INFINEON; Manufacturer PN: IRL7833STRLPBF; PART_NUMBER: 240-0564; Package Size: D2PAK; Package Type: D2PAK; Rated Voltage: 30V
R155 R180 = RES: RES.,10k OHMS,1%,1/10W,0603,AEC-Q200; CLASS: DISCRETE; FPLIST: CR0603N,CR0603L,CR0603M; Inventory Qty: 194448; Manufacturer: VISHAY; Manufacturer PN: CRCW060310K0FKEA; PART_NUMBER: 100-2012; Package Size: 0603; Rated Power: 1/10W; Temperature Coefficient: +/-100ppm/C; Tolerance: 1%
R156 = RES: RES.,10 OHMS,1%,1/10W,0603; CLASS: DISCRETE; FPLIST: CR0603N,CR0603L,CR0603M; Inventory Qty: 152750; Manufacturer: VISHAY; Manufacturer PN: CRCW060310R0FKEA; PART_NUMBER: 100-2306; Package Size: 0603; Rated Power: 1/10W; Temperature Coefficient: 100ppm/C; Tolerance: 1%
R175 R176 = RES: RES., OPTION, 2512; CLASS: DISCRETE; FPLIST: CR2512N,CR2512L,CR2512M,USER_ASSIGNED; PART_NUMBER: 100-2376; Package Size: 2512
R177 = RES: RES.,200 OHMS,1%,1/10W,0603; CLASS: DISCRETE; FPLIST: CR0603N,CR0603L,CR0603M; Inventory Qty: 36974; Label: OPT 0; Manufacturer: VISHAY; Manufacturer PN: CRCW0603200RFKEA; PART_NUMBER: 100-0130; Package Size: 0603; Rated Power: 1/10W; Temperature Coefficient: 100ppm; Tolerance: 1%
R178 R179 = RES: RES.,127 OHMS,1%,1/10W,0603,AEC-Q200; CLASS: DISCRETE; FPLIST: CR0603N,CR0603L,CR0603M; Inventory Qty: 79992; Label: OPT 0; Manufacturer: NIC; Manufacturer PN: NRC06F1270TRF; PART_NUMBER: 100-0054; Package Size: 0603; Rated Power: 1/10W; Temperature Coefficient: 100ppm/C; Tolerance: 1%
R181-R183 = RES: RES.,0.003 OHM,1%,1W,2512,+/-350ppm,METAL, SENSE; CLASS: DISCRETE; FPLIST: CR2512N,CR2512L,CR2512M; Inventory Qty: 1481; Manufacturer: PANASONIC; Manufacturer PN: ERJM1WSF3M0U; PART_NUMBER: 100-0509; Package Size: 2512; Rated Power: 1W; Temperature Coefficient: +/-350ppm; Tolerance: 1%
R184 R185 = RES: RES.,0 OHM,1W,2512,SENSE,COPPER; CLASS: DISCRETE; Inventory Qty: 7479; Manufacturer: VISHAY; Manufacturer PN: WSL251200000ZEA9; PART_NUMBER: 100-0588; Package Size: 2512; Rated Power: 1W; Temperature Coefficient: 3900ppm
R186 R187 = RES: RES.,4.99k OHMS,1%,1/10W,0603,AEC-Q200; CLASS: DISCRETE; FPLIST: CR0603N,CR0603L,CR0603M; Inventory Qty: 89391; Manufacturer: PANASONIC; Manufacturer PN: ERJ3EKF4991V; PART_NUMBER: 100-2510; Package Size: 0603; Rated Power: 1/10W; Temperature Coefficient: 100ppm; Tolerance: 1%
SW1 = SW-DPDT-JS202011CQN_ALT1: SWITCH,SLIDE,DPDT,0.3A,6VDC,PTH; CLASS: DISCRETE; Inventory Qty: 32171; Manufacturer: C&K; Manufacturer PN: JS202011CQN; PART_FIELD_01: ON; PART_FIELD_02: OFF; PART_FIELD_03: RUN; PART_NUMBER: 430-0039
U5 = 24LC025-I_ST_TSSOP-8: IC, MEMORY,EEPROM,2Kb (256x8),TSSOP-8,400kHz; CLASS: IC; FPLIST: TSSOP-8N,TSSOP-8L,TSSOP-8M,MICROCHIP-TSSOP-8; Inventory Qty: 19510; Manufacturer: Microchip; PART_NUMBER: 380-0087; Package Size: TSSOP-8; Package Type: TSSOP-8
LB1 = BLANK_LABEL: LABEL SPEC, DEMO BOARD SERIAL NUMBER; Inventory Qty: 0; Manufacturer: BRADY; Manufacturer PN: THT-96-717-10; PART_NUMBER: 895-0154
MP1-MP4 = MP-PINNED: STANDOFF,NYLON,SNAP-ON,0.25" (6.4mm); CLASS: DISCRETE; Inventory Qty: 227624; Manufacturer: KEYSTONE; Manufacturer PN: 8831; PART_NUMBER: 763-0006
PCB1 = BLANK_PCB_ATE: CLASS: DISCRETE; Inventory Qty: 0; Manufacturer: ADI APPROVED SUPPLIER; Manufacturer PN: 600-DC3082A; PART_NUMBER: 600-DC3082A
STNCL1 = BLANK_STENCIL_PART: BOM Notes: REV01; CLASS: DISCRETE; Inventory Qty: 2; Manufacturer: ADI APPROVED SUPPLIER; Manufacturer PN: 830-DC3082A; PART_NUMBER: 830-DC3082A

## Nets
3V3: E20.1 J28.5(LGKPWR) Q1.3(D) Q7.2(S) Q9.2(S) R177.1
GND: C50.1 C51.1 C52.1 C55.1 C58.1 C61.1 C64.1 C67.1 C70.1 C73.1 C74.1 C75.1 C76.1 C79.1 C82.1 C85.1 C88.1 C92.1 C95.1 C98.1 C99.1 C100.2 C101.2 C102.2 C103.1 CIN23.1 CIN24.1 CIN25.1 CIN26.1 CIN27.1 CIN28.1 CIN29.1 CIN30.1 CIN31.1 CIN32.1 CIN33.1 CIN34.1 CIN35.1 CIN36.1 CIN37.1 CIN38.1 CO57.2 CO58.2 CO59.2 CO60.2 CO61.2 CO62.2 CO63.2 CO64.2 CO65.2 CO66.2 CO67.2 CO68.2 CO69.2 CO70.2 CO71.2 CO72.2 CO73.2 CO74.2 CO75.2 CO76.2 CO77.2 CO78.2 CO79.2 CO80.2 CO81.2 CO82.2 CO83.2 CO84.2 CO85.2 CO86.2 CO87.2 CO88.2 CO89.2 CO90.2 CO91.2 CO92.2 CO93.2 CO94.2 CO95.2 CO96.2 CO97.2 CO98.2 CO99.2 CO100.2 CO101.2 CO102.2 CO103.2 CO104.2 CO105.2 CO106.2 CO107.2 CO108.2 CO109.2 CO110.2 CO111.2 CO112.2 E29.1 E30.1 E31.1 E32.1 E34.1 J8.1 J9.1 J10.1 J11.2 J11.3 J11.4 J11.5 J13.2 J13.3 J13.4 J13.5 J27.2(GND) J28.3(GND) J28.10(GND) Q3.2(S) R90.2 R126.2 R166.2 R175.2 R176.2 R178.2 R179.2 R180.2 R181.2 R182.2 R183.2 SW1.3 U3.A1(GND) U3.A2(GND) U3.A3(GND) U3.A4(GND) U3.A7(GND) U3.A12(GND) U3.AA1(GND) U3.AA2(GND) U3.AA3(GND) U3.AA4(GND) U3.AA7(GND) U3.AA12(GND) U3.AB1(GND) U3.AB2(GND) U3.AB3(GND) U3.AB4(GND) U3.AB7(GND) U3.AB12(GND) U3.B1(GND) U3.B2(GND) U3.B3(GND) U3.B4(GND) U3.B7(GND) U3.B12(GND) U3.C3(GND) U3.C4(GND) U3.C7(GND) U3.C12(GND) U3.D3(GND) U3.D4(GND) U3.D7(GND) U3.D12(GND) U3.E3(GND) U3.E4(GND) U3.E7(GND) U3.E12(GND) U3.F1(GND) U3.F2(GND) U3.F3(GND) U3.F4(GND) U3.F7(GND) U3.F12(GND) U3.G3(GND) U3.G4(GND) U3.G7(GND) U3.G12(GND) U3.H3(GND) U3.H4(GND) U3.H7(GND) U3.H12(GND) U3.J3(GND) U3.J4(GND) U3.J7(GND) U3.J12(GND) U3.K1(GND) U3.K2(GND) U3.K3(GND) U3.K4(GND) U3.K7(GND) U3.K8(GND) U3.K9(GND) U3.K10(GND) U3.K11(GND) U3.K12(GND) U3.L1(GND) U3.L2(GND) U3.L3(GND) U3.L4(GND) U3.L5(GND) U3.L6(GND) U3.L7(GND) U3.L8(GND) U3.L9(GND) U3.L10(GND) U3.L11(GND) U3.L12(GND) U3.L13(GND) U3.L14(GND) U3.L15(GND) U3.M1(GND) U3.M2(GND) U3.M3(GND) U3.M4(GND) U3.M5(GND) U3.M6(GND) U3.M7(GND) U3.M8(GND) U3.M9(GND) U3.M10(GND) U3.M11(GND) U3.M12(GND) U3.M13(GND) U3.M14(GND) U3.M15(GND) U3.N1(GND) U3.N2(GND) U3.N3(GND) U3.N4(GND) U3.N7(GND) U3.N8(GND) U3.N12(GND) U3.P3(GND) U3.P4(GND) U3.P7(GND) U3.P12(GND) U3.R3(GND) U3.R4(GND) U3.R7(GND) U3.R12(GND) U3.T3(GND) U3.T4(GND) U3.T7(GND) U3.T12(GND) U3.U1(GND) U3.U2(GND) U3.U3(GND) U3.U4(GND) U3.U7(GND) U3.U12(GND) U3.V3(GND) U3.V4(GND) U3.V7(GND) U3.V12(GND) U3.W3(GND) U3.W4(GND) U3.W7(GND) U3.W12(GND) U3.Y3(GND) U3.Y4(GND) U3.Y7(GND) U3.Y12(GND) U4.A1(GND) U4.A2(GND) U4.A3(GND) U4.A4(GND) U4.A7(GND) U4.A12(GND) U4.AA1(GND) U4.AA2(GND) U4.AA3(GND) U4.AA4(GND) U4.AA7(GND) U4.AA12(GND) U4.AB1(GND) U4.AB2(GND) U4.AB3(GND) U4.AB4(GND) U4.AB7(GND) U4.AB12(GND) U4.B1(GND) U4.B2(GND) U4.B3(GND) U4.B4(GND) U4.B7(GND) U4.B12(GND) U4.C3(GND) U4.C4(GND) U4.C7(GND) U4.C12(GND) U4.D3(GND) U4.D4(GND) U4.D7(GND) U4.D12(GND) U4.E3(GND) U4.E4(GND) U4.E7(GND) U4.E12(GND) U4.F1(GND) U4.F2(GND) U4.F3(GND) U4.F4(GND) U4.F7(GND) U4.F12(GND) U4.G3(GND) U4.G4(GND) U4.G7(GND) U4.G12(GND) U4.H3(GND) U4.H4(GND) U4.H7(GND) U4.H12(GND) U4.J3(GND) U4.J4(GND) U4.J7(GND) U4.J12(GND) U4.K1(GND) U4.K2(GND) U4.K3(GND) U4.K4(GND) U4.K7(GND) U4.K8(GND) U4.K9(GND) U4.K10(GND) U4.K11(GND) U4.K12(GND) U4.L1(GND) U4.L2(GND) U4.L3(GND) U4.L4(GND) U4.L5(GND) U4.L6(GND) U4.L7(GND) U4.L8(GND) U4.L9(GND) U4.L10(GND) U4.L11(GND) U4.L12(GND) U4.L13(GND) U4.L14(GND) U4.L15(GND) U4.M1(GND) U4.M2(GND) U4.M3(GND) U4.M4(GND) U4.M5(GND) U4.M6(GND) U4.M7(GND) U4.M8(GND) U4.M9(GND) U4.M10(GND) U4.M11(GND) U4.M12(GND) U4.M13(GND) U4.M14(GND) U4.M15(GND) U4.N1(GND) U4.N2(GND) U4.N3(GND) U4.N4(GND) U4.N7(GND) U4.N8(GND) U4.N12(GND) U4.P3(GND) U4.P4(GND) U4.P7(GND) U4.P12(GND) U4.R3(GND) U4.R4(GND) U4.R7(GND) U4.R12(GND) U4.T3(GND) U4.T4(GND) U4.T7(GND) U4.T12(GND) U4.U1(GND) U4.U2(GND) U4.U3(GND) U4.U4(GND) U4.U7(GND) U4.U12(GND) U4.V3(GND) U4.V4(GND) U4.V7(GND) U4.V12(GND) U4.W3(GND) U4.W4(GND) U4.W7(GND) U4.W12(GND) U4.Y3(GND) U4.Y4(GND) U4.Y7(GND) U4.Y12(GND) U5.1(A0) U5.2(A1) U5.3(A2) U5.4(VSS) U5.7(WP) ; also on sheet 5 6
GND_SIGNAL: C56.1 C57.1 C59.1 C60.1 C63.1 C66.1 C69.1 C72.1 C80.1 C81.1 C83.1 C84.1 C87.1 C91.1 C94.1 C97.1 E28.1 R94.1 R96.1 R98.1 R100.1 R102.1 R104.1 R108.1 R110.1 R112.1 R114.1 R116.1 R118.1 R130.1 R132.1 R134.1 R136.1 R138.1 R140.1 R144.1 R146.1 R148.1 R150.1 R152.1 R153.1 U3.F10(SGND_01) U3.F11(SGND_01) U3.U10(SGND_23) U3.U11(SGND_23) U4.F10(SGND_01) U4.F11(SGND_01) U4.U10(SGND_23) U4.U11(SGND_23) ; also on sheet 5 6
SVIN_01A: R157.1 ; also on sheet 6
SVIN_01B: R159.1 ; also on sheet 5
SVIN_01C: C51.2 R84.2 R161.1 U3.J8(SVIN_01)
SVIN_01D: C75.2 R120.2 R163.1 U4.J8(SVIN_01)
SVIN_23A: R158.1 ; also on sheet 6
SVIN_23B: R160.1 ; also on sheet 5
SVIN_23C: C52.2 R85.2 R162.1 U3.P11(SVIN_23)
SVIN_23D: C76.2 R121.2 R164.1 U4.P11(SVIN_23)
VDD25_01A: E9.1 ; also on sheet 6
VDD25_01C: C57.2 R93.2 R95.2 R97.2 R99.2 R101.2 R103.2 U3.C8(VDD25_01)
VDD25_01D: C81.2 R129.2 R131.2 R133.2 R135.2 R137.2 R139.2 U4.C8(VDD25_01)
VDD25_23A: E10.1 ; also on sheet 6
VDD25_23C: C60.2 R107.2 R109.2 R111.2 R113.2 R115.2 R117.2 U3.AB11(VDD25_23)
VDD25_23D: C84.2 R143.2 R145.2 R147.2 R149.2 R151.2 R154.2 U4.AB11(VDD25_23)
VDD33_01A: D4.1(C) E7.1 R155.2 R167.2 ; also on sheet 6
VDD33_01B: R169.2 ; also on sheet 5
VDD33_01C: C56.2 R171.2 U3.E8(VDD33_01)
VDD33_01D: C80.2 R173.2 U4.E8(VDD33_01)
VDD33_23A: D5.1(C) E8.1 R168.2 ; also on sheet 6
VDD33_23B: R170.2 ; also on sheet 5
VDD33_23C: C59.2 R172.2 U3.Y10(VDD33_23)
VDD33_23D: C83.2 R174.2 U4.Y10(VDD33_23)
VIN: R1C.1 R1D.1 R2C.1 R2D.1 R83.1 R84.1 R85.1 R86.1 R88.1 R119.1 R120.1 R121.1 R122.1 R124.1 R165.1 ; also on sheet 5 6
VIN01_C: CIN23.2 CIN24.2 CIN25.2 CIN26.2 R1C.2 R87.1 U3.A5(VIN01) U3.A6(VIN01) U3.B5(VIN01) U3.B6(VIN01) U3.C5(VIN01) U3.C6(VIN01) U3.D5(VIN01) U3.D6(VIN01) U3.E5(VIN01) U3.E6(VIN01) U3.F5(VIN01) U3.F6(VIN01) U3.G5(VIN01) U3.G6(VIN01) U3.H5(VIN01) U3.H6(VIN01) U3.J5(VIN01) U3.J6(VIN01) U3.K5(VIN01) U3.K6(VIN01)
VIN01_D: CIN31.2 CIN32.2 CIN33.2 CIN34.2 R1D.2 R123.1 U4.A5(VIN01) U4.A6(VIN01) U4.B5(VIN01) U4.B6(VIN01) U4.C5(VIN01) U4.C6(VIN01) U4.D5(VIN01) U4.D6(VIN01) U4.E5(VIN01) U4.E6(VIN01) U4.F5(VIN01) U4.F6(VIN01) U4.G5(VIN01) U4.G6(VIN01) U4.H5(VIN01) U4.H6(VIN01) U4.J5(VIN01) U4.J6(VIN01) U4.K5(VIN01) U4.K6(VIN01)
VIN23_C: CIN27.2 CIN28.2 CIN29.2 CIN30.2 R2C.2 R89.1 U3.AA5(VIN23) U3.AA6(VIN23) U3.AB5(VIN23) U3.AB6(VIN23) U3.N5(VIN23) U3.N6(VIN23) U3.P5(VIN23) U3.P6(VIN23) U3.R5(VIN23) U3.R6(VIN23) U3.T5(VIN23) U3.T6(VIN23) U3.U5(VIN23) U3.U6(VIN23) U3.V5(VIN23) U3.V6(VIN23) U3.W5(VIN23) U3.W6(VIN23) U3.Y5(VIN23) U3.Y6(VIN23)
VIN23_D: CIN35.2 CIN36.2 CIN37.2 CIN38.2 R2D.2 R125.1 U4.AA5(VIN23) U4.AA6(VIN23) U4.AB5(VIN23) U4.AB6(VIN23) U4.N5(VIN23) U4.N6(VIN23) U4.P5(VIN23) U4.P6(VIN23) U4.R5(VIN23) U4.R6(VIN23) U4.T5(VIN23) U4.T6(VIN23) U4.U5(VIN23) U4.U6(VIN23) U4.V5(VIN23) U4.V6(VIN23) U4.W5(VIN23) U4.W6(VIN23) U4.Y5(VIN23) U4.Y6(VIN23)
ALERTB: E25.1 J28.6(ALERTB) Q7.1(G) U3.C11(ALERTB_01) U3.W8(ALERTB_23) U4.C11(ALERTB_01) U4.W8(ALERTB_23) ; also on sheet 5 6
AUXP: C103.2 E21.1 J28.1(AUXP) R186.2 R187.2 U5.8(VCC)
AUXSCL: J28.11(AUXSCL) R186.1 U5.6(SCL)
AUXSDA: J28.12(AUXSDA) R187.1 U5.5(SDA)
COMPa: U3.G9(COMP1a) U3.G11(COMP0a) U3.T8(COMP2a) U3.V11(COMP3a) U4.G9(COMP1a) U4.G11(COMP0a) U4.T8(COMP2a) U4.V11(COMP3a) ; also on sheet 5 6
COMPb: C63.2 C66.2 C69.2 C72.2 C87.2 C91.2 C94.2 C97.2 U3.F9(COMP1b) U3.G10(COMP0b) U3.T9(COMP2b) U3.W11(COMP3b) U4.F9(COMP1b) U4.G10(COMP0b) U4.T9(COMP2b) U4.W11(COMP3b) ; also on sheet 5 6
FAULTB: E24.1 Q9.1(G) U3.A10(FAULT1B) U3.A11(FAULT0B) U3.V10(FAULT2B) U3.W10(FAULT3B) U4.A10(FAULT1B) U4.A11(FAULT0B) U4.V10(FAULT2B) U4.W10(FAULT3B) ; also on sheet 5 6
INTVCC_01A: E5.1 R157.2 ; also on sheet 6
INTVCC_01B: E11.1 R159.2 ; also on sheet 5
INTVCC_01C: C55.2 E13.1 R161.2 U3.J9(INTVCC_01)
INTVCC_01D: C79.2 E15.1 R163.2 U4.J9(INTVCC_01)
INTVCC_23A: E6.1 R158.2 ; also on sheet 6
INTVCC_23B: E12.1 R160.2 ; also on sheet 5
INTVCC_23C: C58.2 E14.1 R162.2 U3.P10(INTVCC_23)
INTVCC_23D: C82.2 E16.1 R164.2 U4.P10(INTVCC_23)
PGOOD: E19.1 Q3.1(G) U3.H8(PGOOD1) U3.H9(PGOOD0) U3.R10(PGOOD2) U3.T10(PGOOD3) U4.H8(PGOOD1) U4.H9(PGOOD0) U4.R10(PGOOD2) U4.T10(PGOOD3) ; also on sheet 5 6
RUN: E17.1 R155.1 R156.2 SW1.1 SW1.2 U3.B10(RUN0) U3.B11(RUN1) U3.Y8(RUN3) U3.Y9(RUN2) U4.B10(RUN0) U4.B11(RUN1) U4.Y8(RUN3) U4.Y9(RUN2) ; also on sheet 5 6
RUNP: E18.1 U3.N11(RUNP) U4.N11(RUNP) ; also on sheet 5 6
SCL: E23.1 J27.3(SCL) J28.4(SCL) U3.D10(SCL_01) U3.W9(SCL_23) U4.D10(SCL_01) U4.W9(SCL_23) ; also on sheet 5 6
SDA: E22.1 J27.1(SDA) J28.2(SDA) U3.C10(SDA_01) U3.V8(SDA_23) U4.C10(SDA_01) U4.V8(SDA_23) ; also on sheet 5 6
SHARE_CLK: E26.1 U3.AA11(SHARE_CLK_23) U3.D8(SHARE_CLK_01) U4.AA11(SHARE_CLK_23) U4.D8(SHARE_CLK_01) ; also on sheet 5 6
SYNC: E27.1 U3.D11(SYNC_01) U3.V9(SYNC_23) U4.D11(SYNC_01) U4.V9(SYNC_23) ; also on sheet 5 6
VBIAS_C: C61.2 R90.1 U3.N10(VBIAS)
VBIAS_D: C85.2 R126.1 U4.N10(VBIAS)
VOSNS+: C62.2 C65.2 C68.2 C71.2 C86.2 C89.2 C93.2 C96.2 U3.G8(VOSNS1+) U3.J11(VOSNS0+) U3.P8(VOSNS2+) U3.R11(VOSNS3+) U4.G8(VOSNS1+) U4.J11(VOSNS0+) U4.P8(VOSNS2+) U4.R11(VOSNS3+) ; also on sheet 5 6
VOSNS-: C62.1 C65.1 C68.1 C71.1 C86.1 C89.1 C93.1 C96.1 U3.F8(VOSNS1-) U3.H11(VOSNS0-) U3.R8(VOSNS2-) U3.T11(VOSNS3-) U4.F8(VOSNS1-) U4.H11(VOSNS0-) U4.R8(VOSNS2-) U4.T11(VOSNS3-) ; also on sheet 5 6
VOUT: C102.1 CO57.1 CO58.1 CO59.1 CO60.1 CO61.1 CO62.1 CO63.1 CO64.1 CO65.1 CO66.1 CO67.1 CO68.1 CO69.1 CO70.1 CO71.1 CO72.1 CO73.1 CO74.1 CO75.1 CO76.1 CO77.1 CO78.1 CO79.1 CO80.1 CO81.1 CO82.1 CO83.1 CO84.1 CO85.1 CO86.1 CO87.1 CO88.1 CO89.1 CO90.1 CO91.1 CO92.1 CO93.1 CO94.1 CO95.1 CO96.1 CO97.1 CO98.1 CO99.1 CO100.1 CO101.1 CO102.1 CO103.1 CO104.1 CO105.1 CO106.1 CO107.1 CO108.1 CO109.1 CO110.1 CO111.1 CO112.1 J5.1 J6.1 J7.1 J11.1 R175.1 R176.1 R184.2 R185.2 U3.A13(VOUT0) U3.A14(VOUT0) U3.A15(VOUT0) U3.AA13(VOUT6) U3.AA14(VOUT3) U3.AA15(VOUT3) U3.AB13(VOUT3) U3.AB14(VOUT3) U3.AB15(VOUT3) U3.B13(VOUT0) U3.B14(VOUT0) U3.B15(VOUT0) U3.C13(VOUT0) U3.C14(VOUT0) U3.C15(VOUT0) U3.D13(VOUT0) U3.D14(VOUT0) U3.D15(VOUT0) U3.E13(VOUT0) U3.E14(VOUT0) U3.E15(VOUT0) U3.F13(VOUT1) U3.F14(VOUT1) U3.F15(VOUT1) U3.G13(VOUT1) U3.G14(VOUT1) U3.G15(VOUT1) U3.H13(VOUT1) U3.H14(VOUT1) U3.H15(VOUT1) U3.J13(VOUT1) U3.J14(VOUT1) U3.J15(VOUT1) U3.K13(VOUT1) U3.K14(VOUT1) U3.K15(VOUT1) U3.N13(VOUT2) U3.N14(VOUT2) U3.N15(VOUT2) U3.P13(VOUT2) U3.P14(VOUT2) U3.P15(VOUT2) U3.R13(VOUT2) U3.R14(VOUT2) U3.R15(VOUT2) U3.T13(VOUT2) U3.T14(VOUT2) U3.T15(VOUT2) U3.U13(VOUT2) U3.U14(VOUT2) U3.U15(VOUT2) U3.V13(VOUT3) U3.V14(VOUT3) U3.V15(VOUT3) U3.W13(VOUT3) U3.W14(VOUT3) U3.W15(VOUT3) U3.Y13(VOUT3) U3.Y14(VOUT3) U3.Y15(VOUT3) U4.A13(VOUT0) U4.A14(VOUT0) U4.A15(VOUT0) U4.AA13(VOUT6) U4.AA14(VOUT3) U4.AA15(VOUT3) U4.AB13(VOUT3) U4.AB14(VOUT3) U4.AB15(VOUT3) U4.B13(VOUT0) U4.B14(VOUT0) U4.B15(VOUT0) U4.C13(VOUT0) U4.C14(VOUT0) U4.C15(VOUT0) U4.D13(VOUT0) U4.D14(VOUT0) U4.D15(VOUT0) U4.E13(VOUT0) U4.E14(VOUT0) U4.E15(VOUT0) U4.F13(VOUT1) U4.F14(VOUT1) U4.F15(VOUT1) U4.G13(VOUT1) U4.G14(VOUT1) U4.G15(VOUT1) U4.H13(VOUT1) U4.H14(VOUT1) U4.H15(VOUT1) U4.J13(VOUT1) U4.J14(VOUT1) U4.J15(VOUT1) U4.K13(VOUT1) U4.K14(VOUT1) U4.K15(VOUT1) U4.N13(VOUT2) U4.N14(VOUT2) U4.N15(VOUT2) U4.P13(VOUT2) U4.P14(VOUT2) U4.P15(VOUT2) U4.R13(VOUT2) U4.R14(VOUT2) U4.R15(VOUT2) U4.T13(VOUT2) U4.T14(VOUT2) U4.T15(VOUT2) U4.U13(VOUT2) U4.U14(VOUT2) U4.U15(VOUT2) U4.V13(VOUT3) U4.V14(VOUT3) U4.V15(VOUT3) U4.W13(VOUT3) U4.W14(VOUT3) U4.W15(VOUT3) U4.Y13(VOUT3) U4.Y14(VOUT3) U4.Y15(VOUT3) ; also on sheet 5 6
WP: U3.E9(WP_01) U3.Y11(WP_23) U4.E9(WP_01) U4.Y11(WP_23) ; also on sheet 5 6
N22587106: C50.2 R83.2 U3.N9(VIN_VBIAS)
N22587110: C53.2 R86.2 U3.H10(IN_01+)
N22587111: C53.1 R87.2 U3.J10(IN_01-)
N22587124: C54.2 R88.2 U3.R9(IN_23+)
N22587125: C54.1 R89.2 U3.P9(IN_23-)
N22587297: R91.1 TP9.1(A) U3.C1(SW0) U3.C2(SW0) U3.D1(SW0) U3.D2(SW0) U3.E1(SW0) U3.E2(SW0)
N22587361: R92.1 TP10.1(A) U3.G1(SW1) U3.G2(SW1) U3.H1(SW1) U3.H2(SW1) U3.J1(SW1) U3.J2(SW1)
N22587368: C67.2 R92.2
N22587382: R95.1 R96.2 U3.A8(VOUT0_CFG)
N22587385: R97.1 R98.2 U3.B8(VOUT1_CFG)
N22587388: R99.1 R100.2 U3.D9(VTRIM0_CFG)
N22587391: R101.1 R102.2 U3.C9(VTRIM1_CFG)
N22587394: R103.1 R104.2 U3.A9(FSWPH_01_CFG)
N22587396: R93.1 R94.2 U3.B9(ASEL_01)
N22587452: TP26.1(A) U3.E10(TSNS1)
N22587497: R105.1 TP11.1(A) U3.P1(SW2) U3.P2(SW2) U3.R1(SW2) U3.R2(SW2) U3.T1(SW2) U3.T2(SW2)
N22587553: R106.1 TP12.1(A) U3.V1(SW3) U3.V2(SW3) U3.W1(SW3) U3.W2(SW3) U3.Y1(SW3) U3.Y2(SW3)
N22587564: C73.2 R106.2
N22587573: R107.1 R108.2 U3.AA10(ASEL_23)
N22587576: R111.1 R112.2 U3.AB8(VOUT3_CFG)
N22587584: R113.1 R114.2 U3.AB10(VTRIM2_CFG)
N22587588: R109.1 R110.2 U3.AA8(VOUT2_CFG)
N22587591: R115.1 R116.2 U3.AB9(VTRIM3_CFG)
N22587595: R117.1 R118.2 U3.AA9(FSWPH_23_CFG)
N22587621: TP27.1(A) U3.U8(TSNS2)
N22587627: TP28.1(A) U3.U9(TSNS3)
N22587942: C64.2 R91.2
N22587990: C70.2 R105.2
N22588038: TP25.1(A) U3.E11(TSNS0)
N22594456: C74.2 R119.2 U4.N9(VIN_VBIAS)
N22594460: C77.2 R122.2 U4.H10(IN_01+)
N22594461: C77.1 R123.2 U4.J10(IN_01-)
N22594474: C78.2 R124.2 U4.R9(IN_23+)
N22594475: C78.1 R125.2 U4.P9(IN_23-)
N22594647: R127.1 TP13.1(A) U4.C1(SW0) U4.C2(SW0) U4.D1(SW0) U4.D2(SW0) U4.E1(SW0) U4.E2(SW0)
N22594711: R128.1 TP14.1(A) U4.G1(SW1) U4.G2(SW1) U4.H1(SW1) U4.H2(SW1) U4.J1(SW1) U4.J2(SW1)
N22594718: C92.2 R128.2
N22594732: R131.1 R132.2 U4.A8(VOUT0_CFG)
N22594735: R133.1 R134.2 U4.B8(VOUT1_CFG)
N22594738: R135.1 R136.2 U4.D9(VTRIM0_CFG)
N22594741: R137.1 R138.2 U4.C9(VTRIM1_CFG)
N22594744: R139.1 R140.2 U4.A9(FSWPH_01_CFG)
N22594746: R129.1 R130.2 U4.B9(ASEL_01)
N22594802: TP30.1(A) U4.E10(TSNS1)
N22594847: R141.1 TP15.1(A) U4.P1(SW2) U4.P2(SW2) U4.R1(SW2) U4.R2(SW2) U4.T1(SW2) U4.T2(SW2)
N22594903: R142.1 TP16.1(A) U4.V1(SW3) U4.V2(SW3) U4.W1(SW3) U4.W2(SW3) U4.Y1(SW3) U4.Y2(SW3)
N22594914: C98.2 R142.2
N22594923: R143.1 R144.2 U4.AA10(ASEL_23)
N22594926: R147.1 R148.2 U4.AB8(VOUT3_CFG)
N22594934: R149.1 R150.2 U4.AB10(VTRIM2_CFG)
N22594938: R145.1 R146.2 U4.AA8(VOUT2_CFG)
N22594941: R151.1 R152.2 U4.AB9(VTRIM3_CFG)
N22594945: R153.2 R154.1 U4.AA9(FSWPH_23_CFG)
N22594971: TP31.1(A) U4.U8(TSNS2)
N22594977: TP32.1(A) U4.U9(TSNS3)
N22595290: C88.2 R127.2
N22595338: C95.2 R141.2
N22595384: TP29.1(A) U4.E11(TSNS0)
N22607862: Q1.2(S) R167.1 R168.1 R169.1 R170.1 R171.1 R172.1 R173.1 R174.1
N22607872: Q1.1(G) R165.2 R166.1
N22607996: C100.1 C101.1 Q13.2(D) Q14.2(D) Q17.2(D) R184.1 R185.1
N22608016: E33.1 Q13.1(G) Q14.1(G) Q17.1(G) R180.1
N22608019: J13.1 Q13.3(S) Q14.3(S) Q17.3(S) R181.1 R182.1 R183.1
N22608048: D1.2(ANODE) R177.2
N22608050: D1.1(CATHODE) Q3.3(D)
N22608068: D3.2(ANODE) Q7.3(D)
N22608069: D2.2(ANODE) Q9.3(D)
N22608071: D3.1(CATHODE) R179.1
N22608085: D2.1(CATHODE) R178.1
N22608239: C99.2 R156.1
N22672592: D4.2(A) D5.2(A) J27.4(AUX3V4)

Not connected (* = marked no-connect by the designer): J28 7(GPIO_1)* 8(OUTEN_0) 9(OUTEN_1)*; MP1 1; MP2 1; MP3 1; MP4 1; SW1 4 5 6

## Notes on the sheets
sheet 1
- PCA ADDITIONAL PARTS
sheet 2
- TEST POINTS
- MASTER RUN SWITCH
- OPERATION at LOW VIN RANGE: 4.5V<VIN <5.75V
- OPTIONAL SYSTEM 3V3 /100mA (PROGRAM with NO VIN)
- OPTIONAL BLEEDER  LOADs
- 2512
- 2512
- *SVIN_01[A,B,C,D] , SVIN_23[A,B,C,D] are tied to VIN
- *RUNP is tied to GND (JP1 is set to OFF)
- *Disconnect  all VIN_VBIAS[U1,U2,U3,U4] pins from VIN and short all VBIAS [A,B,C,D] to GND
- *Additional input electrolytic and ceramic caps are required
- OPTIONAL LEDs INDICATION
- OPTIONAL DYNAMIC LOAD STEP CIRCUIT
- PGOOD
- FAULTB
- ALERTB
- DC1613A CONNECTOR and OPTIONAL ONBOARD EEPROM IDENTIFICATION
- TO DC2086A
- TO DC1613A
- m
- m
- b
sheet 3
- 25V
- 25V
- 25V
- EEFGX0E471R
- 0805
- 0805
- 0805
- 0805
- 0805
- 0805
- 0805
- m
sheet 4
- 25V
- 25V
- 25V
- EEFGX0E471R
- 0805
- 0805
- 0805
- 0805
- 0805
- 0805
- m
